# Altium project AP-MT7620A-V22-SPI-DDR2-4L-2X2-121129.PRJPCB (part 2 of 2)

## Sheet 17-GPHY1-IP1001.SchDoc
size 513 x 386 mm
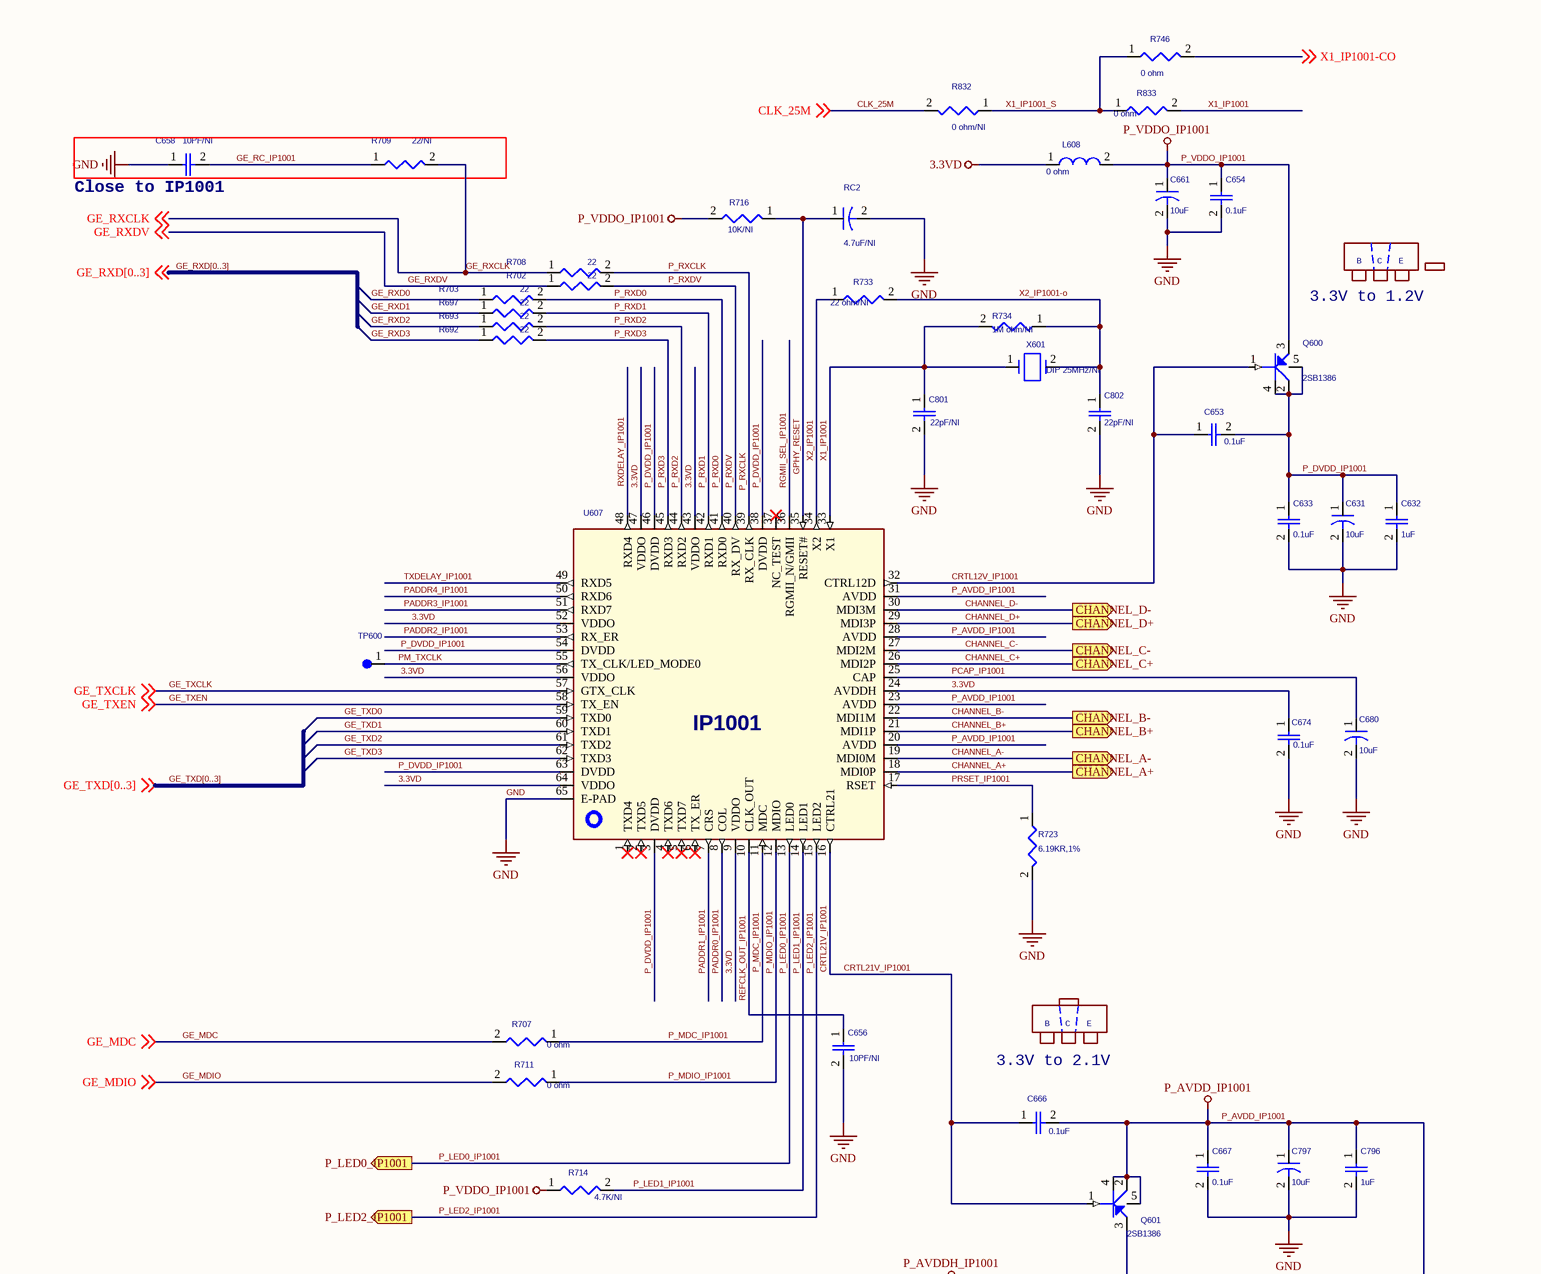
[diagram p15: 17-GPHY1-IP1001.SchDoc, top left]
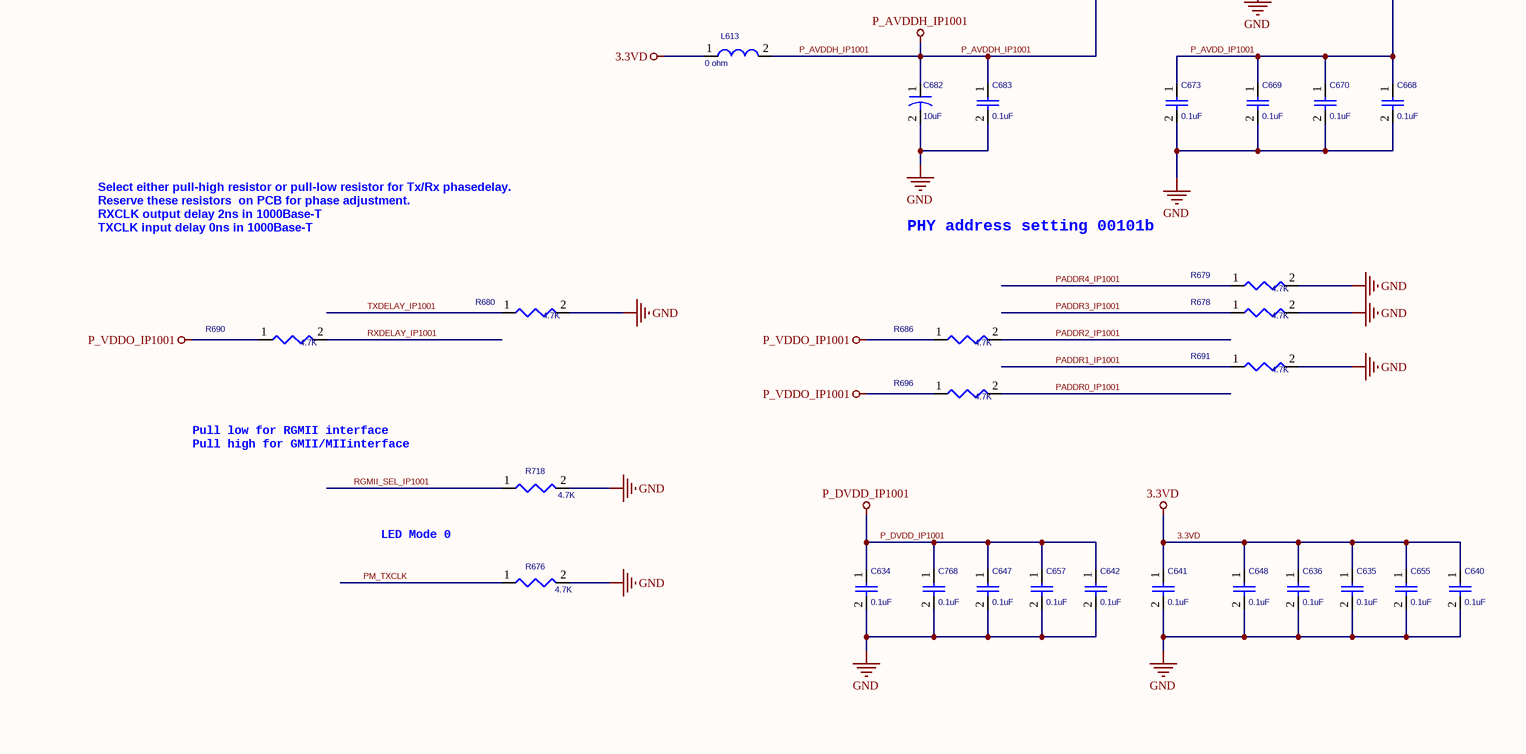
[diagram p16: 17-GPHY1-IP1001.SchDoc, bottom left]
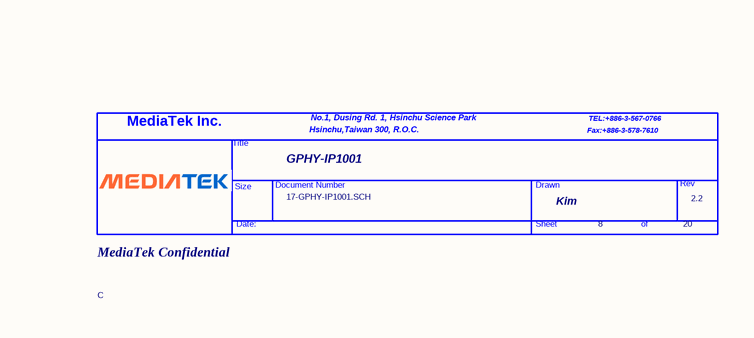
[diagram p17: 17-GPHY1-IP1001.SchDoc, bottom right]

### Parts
(Parts that share a designator on the sheet are numbered #1, #2 ... from top to bottom, then left to right.)
*#13  PIM: MediaTek Confidential  Page Count: 20  Page Number: 8  Page Size: C  Title: GPHY-IP1001  RevCode: 2.2  Doc: 17-GPHY-IP1001.SCH  Designer: Kim  (hidden comment: TitleBlock_MTK4)  (graphical)
C631  10uF  [C0805]
C632  1uF  [C0402]
C633  0.1uF  [C0402]
C634  0.1uF  [C0402]
C635  0.1uF  [C0402]
C636  0.1uF  [C0402]
C640  0.1uF  [C0402]
C641  0.1uF  [C0402]
C642  0.1uF  [C0402]
C647  0.1uF  [C0402]
C648  0.1uF  [C0402]
C653  0.1uF  [C0402]
C654  0.1uF  [C0402]
C655  0.1uF  [C0402]
C656  10PF/NI  [C0402]
C657  0.1uF  [C0402]
C658  10PF/NI  [C0402]
C661  10uF  [C0805]
C666  0.1uF  [C0402]
C667  0.1uF  [C0402]
C668  0.1uF  [C0402]
C669  0.1uF  [C0402]
C670  0.1uF  [C0402]
C673  0.1uF  [C0402]
C674  0.1uF  [C0402]
C680  10uF  [C0805]
C682  10uF  [C0805]
C683  0.1uF  [C0402]
C768  0.1uF  [C0402]
C796  1uF  [C0402]
C797  10uF  [C0805]
C801  22pF/NI  [C0402]
C802  22pF/NI  [C0402]
L608  0 ohm  [L1206]
L613  0 ohm  [L1206]
Q600  2SB1386  [SOT-89/SMD/2SB1386]
Q601  2SB1386  [SOT-89/SMD/2SB1386]
R676  4.7K  [R0402]
R678  4.7K  [R0402]
R679  4.7K  [R0402]
R680  4.7K  [R0402]
R686  4.7K  [R0402]
R690  4.7K  [R0402]
R691  4.7K  [R0402]
R692  22  [R0402]
R693  22  [R0402]
R696  4.7K  [R0402]
R697  22  [R0402]
R702  22  [R0402]
R703  22  [R0402]
R707  0 ohm  [R0402]
R708  22  [R0402]
R709  22/NI  [R0402]
R711  0 ohm  [R0402]
R714  4.7K/NI  [R0402]
R716  10K/NI  [R0402]
R718  4.7K  [R0402]
R723  6.19KR,1%  [R0402]
R733  22 ohm/NI  [R0402]
R734  1M ohm/NI  [R0402]
R746  0 ohm  [R0402]
R832  0 ohm/NI  [R0402]
R833  0 ohm  [R0402]
RC2  4.7uF/NI  [C0603]
TP600  SMD  [PAD/1P/0.5MM]  (value not drawn)
U607  IP1001  [QFN64/SMD/P0.5/IP1001]
X601  DIP 25MHz/NI  [CRYS/DIP/D5X10.6/GB2000025/eCERA]

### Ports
CHANNEL_A+ (out), CHANNEL_A- (out), CHANNEL_B+ (out), CHANNEL_B- (out), CHANNEL_C+ (out), CHANNEL_C- (out), CHANNEL_D+ (out), CHANNEL_D- (out), P_LED0_IP1001 (out), P_LED2_IP1001 (out)

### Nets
3.3VD: C635.1 C636.1 C640.1 C641.1 C648.1 C655.1 C674.1 L608.1 L613.1 U607.9(VDDO) U607.24(AVDDH) U607.43(VDDO) U607.47(VDDO) U607.52(VDDO) U607.56(VDDO) U607.64(VDDO)
GND: C631.2 C632.2 C633.2 C634.2 C635.2 C636.2 C640.2 C641.2 C642.2 C647.2 C648.2 C654.2 C655.2 C656.2 C657.2 C658.1 C661.2 C667.2 C668.2 C669.2 C670.2 C673.2 C674.2 C680.2 C682.2 C683.2 C768.2 C796.2 C797.2 C801.2 C802.2 R676.2 R678.2 R679.2 R680.2 R691.2 R718.2 R723.2 RC2.2 U607.65(E-PAD)
P_AVDD_IP1001: C666.2 C667.1 C668.1 C669.1 C670.1 C673.1 C796.1 C797.1 Q601.2(COLLECTOR) Q601.4(COLLECTOR) Q601.5(COLLECTOR) U607.20(AVDD) U607.23(AVDD) U607.28(AVDD) U607.31(AVDD)
P_AVDDH_IP1001: C682.1 C683.1 L613.2 Q601.3(EMITTER)
P_DVDD_IP1001: C631.1 C632.1 C633.1 C634.1 C642.1 C647.1 C653.2 C657.1 C768.1 Q600.2(COLLECTOR) Q600.4(COLLECTOR) Q600.5(COLLECTOR) U607.3(DVDD) U607.38(DVDD) U607.46(DVDD) U607.54(DVDD) U607.63(DVDD)
P_VDDO_IP1001: C654.1 C661.1 L608.2 Q600.3(EMITTER) R686.1 R690.1 R696.1 R714.1 R716.2
CHANNEL_A+: U607.18(MDI0P) ; port CHANNEL_A+
CHANNEL_A-: U607.19(MDI0M) ; port CHANNEL_A-
CHANNEL_B+: U607.21(MDI1P) ; port CHANNEL_B+
CHANNEL_B-: U607.22(MDI1M) ; port CHANNEL_B-
CHANNEL_C+: U607.26(MDI2P) ; port CHANNEL_C+
CHANNEL_C-: U607.27(MDI2M) ; port CHANNEL_C-
CHANNEL_D+: U607.29(MDI3P) ; port CHANNEL_D+
CHANNEL_D-: U607.30(MDI3M) ; port CHANNEL_D-
CLK_25M: R832.2 ; off-sheet CLK_25M
CRTL12V_IP1001: C653.1 Q600.1(BASE) U607.32(CTRL12D)
CRTL21V_IP1001: C666.1 Q601.1(BASE) U607.16(CTRL21)
GE_MDC: R707.2 ; off-sheet GE_MDC
GE_MDIO: R711.2 ; off-sheet GE_MDIO
GE_RC_IP1001: C658.2 R709.1
GE_RXCLK: R708.1 R709.2 ; off-sheet GE_RXCLK
GE_RXD0: R703.1
GE_RXD1: R697.1
GE_RXD2: R693.1
GE_RXD3: R692.1
GE_RXDV: R702.1 ; off-sheet GE_RXDV
GE_TXCLK: U607.57(GTX_CLK) ; off-sheet GE_TXCLK
GE_TXD0: U607.59(TXD0)
GE_TXD1: U607.60(TXD1)
GE_TXD2: U607.61(TXD2)
GE_TXD3: U607.62(TXD3)
GE_TXEN: U607.58(TX_EN) ; off-sheet GE_TXEN
GPHY_RESET: R716.1 RC2.1 U607.35(RESET#)
P_LED0_IP1001: U607.13(LED0) ; port P_LED0_IP1001
P_LED1_IP1001: R714.2 U607.14(LED1)
P_LED2_IP1001: U607.15(LED2) ; port P_LED2_IP1001
P_MDC_IP1001: R707.1 U607.11(MDC)
P_MDIO_IP1001: R711.1 U607.12(MDIO)
P_RXCLK: R708.2 U607.39(RX_CLK)
P_RXD0: R703.2 U607.41(RXD0)
P_RXD1: R697.2 U607.42(RXD1)
P_RXD2: R693.2 U607.44(RXD2)
P_RXD3: R692.2 U607.45(RXD3)
P_RXDV: R702.2 U607.40(RX_DV)
PADDR0_IP1001: R696.2 U607.8(COL)
PADDR1_IP1001: R691.1 U607.7(CRS)
PADDR2_IP1001: R686.2 U607.53(RX_ER)
PADDR3_IP1001: R678.1 U607.51(RXD7)
PADDR4_IP1001: R679.1 U607.50(RXD6)
PCAP_IP1001: C680.1 U607.25(CAP)
PM_TXCLK: R676.1 TP600.1 U607.55(TX_CLK/LED_MODE0)
PRSET_IP1001: R723.1 U607.17(RSET)
REFCLK_OUT_IP1001: C656.1 U607.10(CLK_OUT)
RGMII_SEL_IP1001: R718.1 U607.36(RGMII_N/GMII)
RXDELAY_IP1001: R690.2 U607.48(RXD4)
TXDELAY_IP1001: R680.1 U607.49(RXD5)
X1_IP1001: C801.1 R734.2 R833.2 U607.33(X1) X601.1
X1_IP1001-CO: R746.2 ; off-sheet X1_IP1001-CO
X1_IP1001_S: R746.1 R832.1 R833.1
X2_IP1001: R733.1 U607.34(X2)
X2_IP1001-o: C802.1 R733.2 R734.1 X601.2

Not connected (* = marked no-connect by the designer): U607 1(TXD4)* 2(TXD5)* 4(TXD6)* 5(TXD7)* 6(TX_ER)* 37(NC_TEST)*

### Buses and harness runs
bus GE_RXD[0..3]
bus GE_TXD[0..3]

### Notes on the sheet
- (near C658) Close to IP1001
- (near Q600) 3.3V to 1.2V
- B
- C
- E
- (near C666) 3.3V to 2.1V
- (near R680) Select either pull-high resistor or pull-low resistor for Tx/Rx phasedelay.
  Reserve these resistors  on PCB for phase adjustment.
  RXCLK output delay 2ns in 1000Base-T
  TXCLK input delay 0ns in 1000Base-T
- PHY address setting 00101b
- (near R718) Pull low for RGMII interface
  Pull high for GMII/MIIinterface
- LED Mode 0

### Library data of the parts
C631 C661 C680 C682 C797 = CAP/0805
C632-C636 C640-C642 C647 C648 C653-C657 C666-C670 C673 C674 C683 C768 C796 C801 C802 = CAP/0402_Dup2
C658 = CAP/0402_Dup1
L608 L613 = L/0805_0603
Q600 = BJT 2SB1386-PNP_2
Q601 = BJT 2SB1386-PNP_3_Dup1
R676 R678-R680 R686 R690-R693 R696 R697 R702 R703 R707-R709 R711 R714 R716 R718 R723 R733 R734 R746 R832 R833 = RES/0402_Dup2
RC2 = CAP/0603_Dup2
TP600 = TP-SMD
U607 = IP1001_0
X601 = CRYSTAL-3x9_0

## Sheet 16-MT7620A Power-F.SchDoc
size 386 x 246 mm
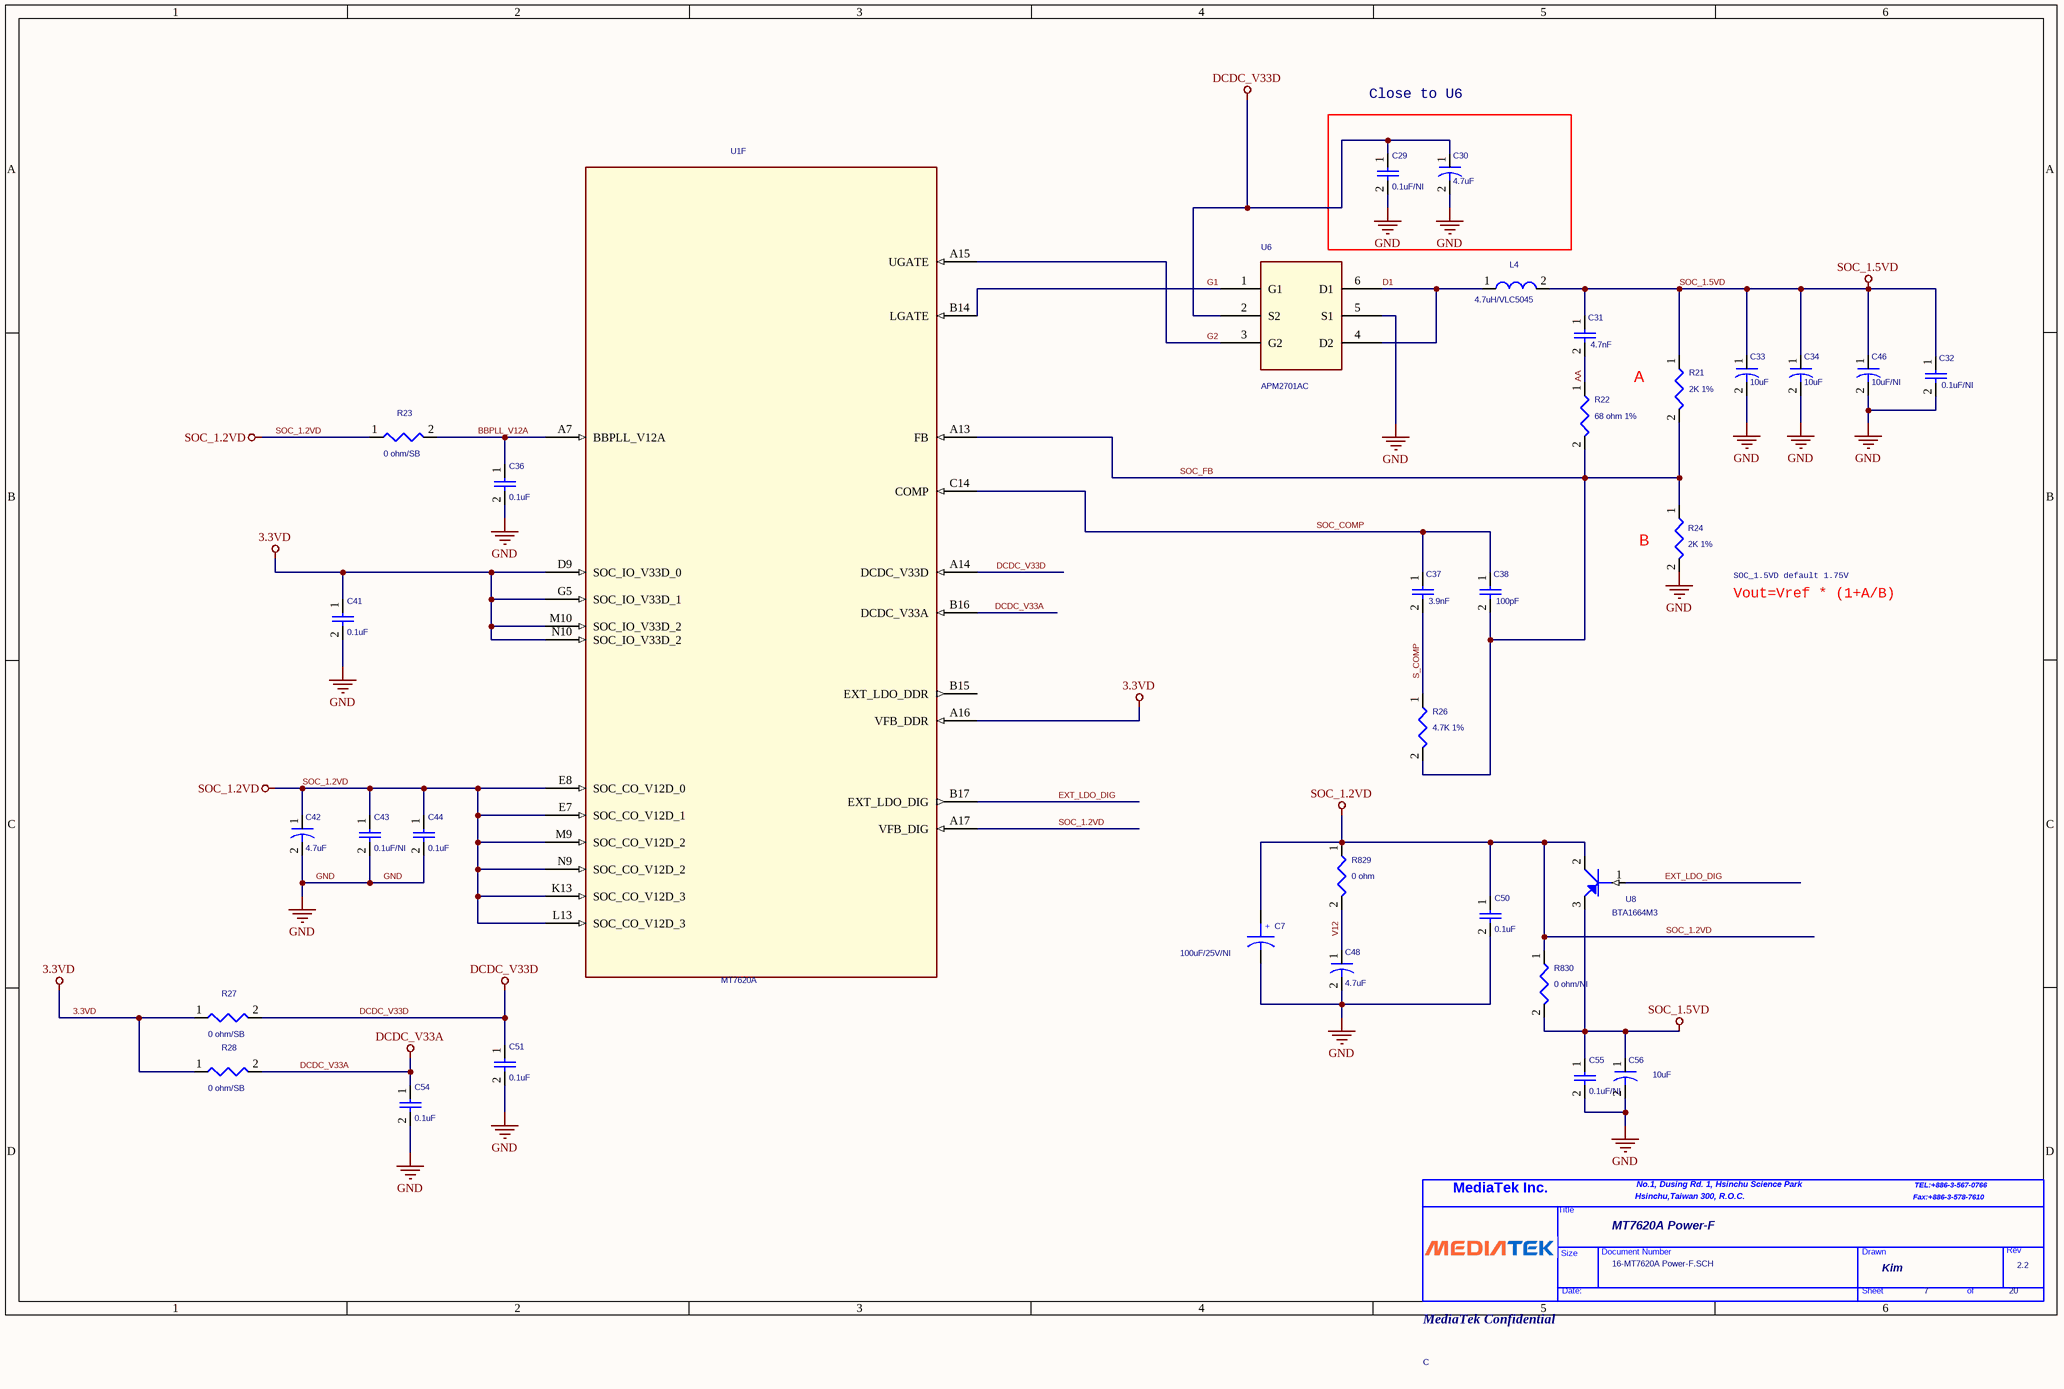
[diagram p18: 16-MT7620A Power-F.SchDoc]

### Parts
(Parts that share a designator on the sheet are numbered #1, #2 ... from top to bottom, then left to right.)
*#14  PIM: MediaTek Confidential  Page Count: 20  Page Number: 7  Page Size: C  Title: MT7620A Power-F  RevCode: 2.2  Doc: 16-MT7620A Power-F.SCH  Designer: Kim  (hidden comment: TitleBlock_MTK4)  (graphical)
C7  100uF/25V/NI  [C100UF25V/D6.3H11.5]
C29  0.1uF/NI  [C0402]
C30  4.7uF  [C0603]
C31  4.7nF  [C0402]
C32  0.1uF/NI  [C0402]
C33  10uF  [C0805]
C34  10uF  [C0805]
C36  0.1uF  [C0402]
C37  3.9nF  [C0402]
C38  100pF  [C0402]
C41  0.1uF  [C0402]
C42  4.7uF  [C0603]
C43  0.1uF/NI  [C0402]
C44  0.1uF  [C0402]
C46  10uF/NI  [C0805]
C48  4.7uF  [C0805]
C50  0.1uF  [C0402]
C51  0.1uF  [C0402]
C54  0.1uF  [C0402]
C55  0.1uF/NI  [C0402]
C56  10uF  [C0805]
L4  4.7uH/VLC5045  [L/IND/SMD/LVS5045]
R21  2K 1%  [R0402]
R22  68 ohm 1%  [R0402]
R23  0 ohm/SB  [SB/0402]
R24  2K 1%  [R0402]
R26  4.7K 1%  [R0402]
R27  0 ohm/SB  [SB/0402]
R28  0 ohm/SB  [SB/0402]
R829  0 ohm  [C0402]
R830  0 ohm/NI  [R0603]
U1  MT7620A  [MT7620AE2/TFBGA265/P0.65/B0.3/11X11]  (part F of 6)
U6  APM2701AC  [SOT-23-6/SMD/P0.95/APM2701AC]
U8  BTA1664M3  [SOT89/SMD]

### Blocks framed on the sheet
Close to U6: C29 C30

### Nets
3.3VD: C41.1 R27.1 R28.1 U1.A16(VFB_DDR) U1.D9(SOC_IO_V33D_0) U1.G5(SOC_IO_V33D_1) U1.M10(SOC_IO_V33D_2) U1.N10(SOC_IO_V33D_2)
DCDC_V33A: C54.1 R28.2 U1.B16(DCDC_V33A)
DCDC_V33D: C29.1 C30.1 C51.1 R27.2 U1.A14(DCDC_V33D) U6.2(S2)
GND: C7.2 C29.2 C30.2 C32.2 C33.2 C34.2 C36.2 C41.2 C42.2 C43.2 C44.2 C46.2 C48.2 C50.2 C51.2 C54.2 C55.2 C56.2 R24.2 U6.5(S1)
SOC_1.2VD: C7.1 C42.1 C43.1 C44.1 C50.1 R23.1 R829.1 R830.1 U1.A17(VFB_DIG) U1.E7(SOC_CO_V12D_1) U1.E8(SOC_CO_V12D_0) U1.K13(SOC_CO_V12D_3) U1.L13(SOC_CO_V12D_3) U1.M9(SOC_CO_V12D_2) U1.N9(SOC_CO_V12D_2) U8.2(COLLECTOR)
SOC_1.5VD: C31.1 C32.1 C33.1 C34.1 C46.1 C55.1 C56.1 L4.2 R21.1 R830.2 U8.3(EMITTER)
AA: C31.2 R22.1
BBPLL_V12A: C36.1 R23.2 U1.A7(BBPLL_V12A)
D1: L4.1 U6.4(D2) U6.6(D1)
EXT_LDO_DIG: U1.B17(EXT_LDO_DIG) U8.1(BASE)
G1: U1.B14(LGATE) U6.1(G1)
G2: U1.A15(UGATE) U6.3(G2)
S_COMP: C37.2 R26.1
SOC_COMP: C37.1 C38.1 U1.C14(COMP)
SOC_FB: C38.2 R21.2 R22.2 R24.1 R26.2 U1.A13(FB)
V12: C48.1 R829.2

Not connected (* = marked no-connect by the designer): U1 B15(EXT_LDO_DDR)

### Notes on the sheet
- A
- (near R24) B
- Vout=Vref * (1+A/B)
- SOC_1.5VD default 1.75V

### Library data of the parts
C7 = CAPACITOR POL
C29 C36 C41 C43 C44 C50 C51 C54 C55 = CAP/0402_0
C30 C33 C34 C46 = CAP/0603_Dup3
C31 C32 C37 C38 = CAP/0402_Dup2: 1st Part Field: 0402
C42 C48 C56 = CAP/1210_1206
L4 = L/GDR1012
R21-R24 R26-R28 R829 R830 = RES/0402_1_Dup1
U8 = BJT 2SB1386-PNP_3

## Sheet 15-MT7620A Ethernet-E.SchDoc
size 513 x 386 mm
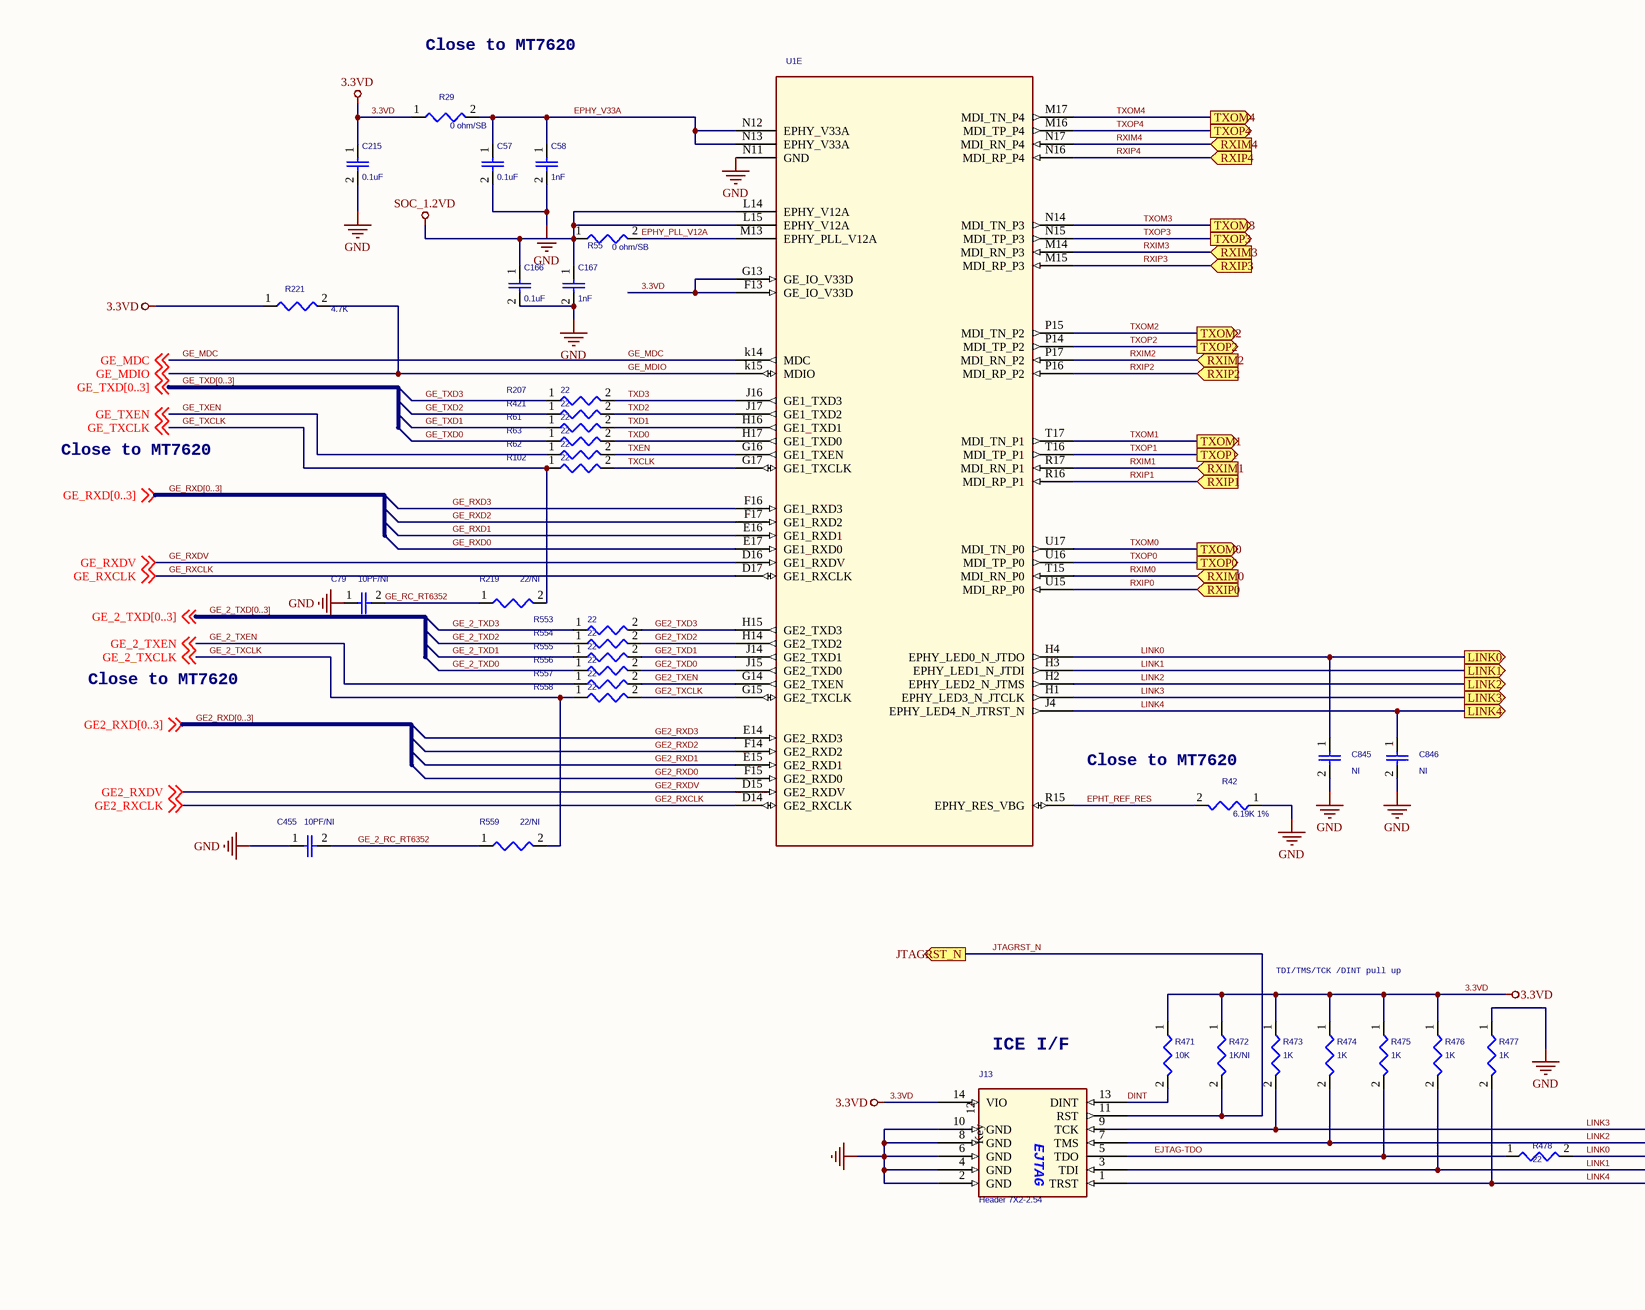
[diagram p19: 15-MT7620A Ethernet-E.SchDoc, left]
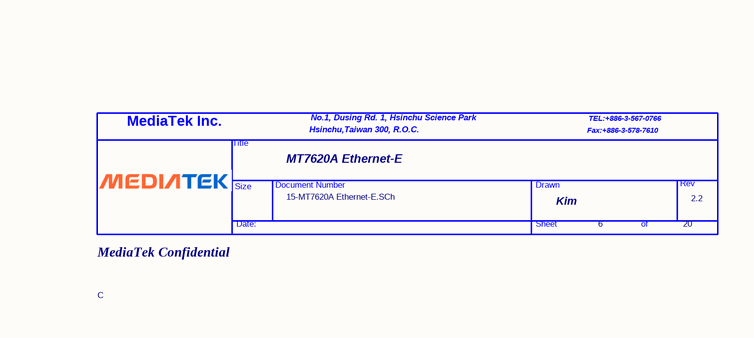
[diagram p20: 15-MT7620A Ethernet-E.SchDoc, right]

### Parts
(Parts that share a designator on the sheet are numbered #1, #2 ... from top to bottom, then left to right.)
*#15  PIM: MediaTek Confidential  Page Count: 20  Page Number: 6  Page Size: C  Title: MT7620A Ethernet-E  RevCode: 2.2  Doc: 15-MT7620A Ethernet-E.SCh  Designer: Kim  (hidden comment: TitleBlock_MTK4)  (graphical)
C57  0.1uF  [C0402]
C58  1nF  [C0402]
C79  10PF/NI  [C0402]
C166  0.1uF  [C0402]
C167  1nF  [C0402]
C215  0.1uF  [C0402]
C455  10PF/NI  [C0402]
C845  NI  [C0402]
C846  NI  [C0402]
J13  Header 7X2-2.54  [DIP7X2/P2.54]
R29  0 ohm/SB  [SB/0402]
R42  6.19K 1%  [R0402]
R55  0 ohm/SB  [SB/0402]
R61  22  [R0402]
R62  22  [R0402]
R63  22  [R0402]
R102  22  [R0402]
R207  22  [R0402]
R219  22/NI  [R0402]
R221  4.7K  [R0402]
R421  22  [R0402]
R471  10K  [R0402]
R472  1K/NI  [R0402]
R473  1K  [R0402]
R474  1K  [R0402]
R475  1K  [R0402]
R476  1K  [R0402]
R477  1K  [R0402]
R478  22  [R0402]
R553  22  [R0402]
R554  22  [R0402]
R555  22  [R0402]
R556  22  [R0402]
R557  22  [R0402]
R558  22  [R0402]
R559  22/NI  [R0402]
U1  (no value)  [MT7620AE2/TFBGA265/P0.65/B0.3/11X11]  (part E of 6)

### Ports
JTAGRST_N (out), LINK0 (out), LINK1 (out), LINK2 (out), LINK3 (out), LINK4 (out), RXIM0 (in), RXIM1 (in), RXIM2 (in), RXIM3 (in), RXIM4 (in), RXIP0 (in), RXIP1 (in), RXIP2 (in), RXIP3 (in), RXIP4 (in), TXOM0 (out), TXOM1 (out), TXOM2 (out), TXOM3 (out), TXOM4 (out), TXOP0 (out), TXOP1 (out), TXOP2 (out), TXOP3 (out), TXOP4 (out)

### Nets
3.3VD: C215.1 J13.14(VIO) R29.1 R221.1 R471.1 R472.1 R473.1 R474.1 R475.1 R476.1 U1.F13(GE_IO_V33D) U1.G13(GE_IO_V33D)
GND: C57.2 C58.2 C79.1 C166.2 C167.2 C215.2 C455.1 C845.2 C846.2 J13.2(GND) J13.4(GND) J13.6(GND) J13.8(GND) J13.10(GND) R42.1 R477.1 U1.N11(GND)
SOC_1.2VD: C166.1 C167.1 R55.1 U1.L14(EPHY_V12A) U1.L15(EPHY_V12A)
DINT: J13.13(DINT) R471.2
EJTAG-TDO: J13.5(TDO) R475.2 R478.1
EPHT_REF_RES: R42.2 U1.R15(EPHY_RES_VBG)
EPHY_PLL_V12A: R55.2 U1.M13(EPHY_PLL_V12A)
EPHY_V33A: C57.1 C58.1 R29.2 U1.N12(EPHY_V33A) U1.N13(EPHY_V33A)
GE2_RXCLK: U1.D14(GE2_RXCLK) ; off-sheet GE2_RXCLK
GE2_RXD0: U1.F15(GE2_RXD0)
GE2_RXD1: U1.E15(GE2_RXD1)
GE2_RXD2: U1.F14(GE2_RXD2)
GE2_RXD3: U1.E14(GE2_RXD3)
GE2_RXDV: U1.D15(GE2_RXDV) ; off-sheet GE2_RXDV
GE2_TXCLK: R558.2 U1.G15(GE2_TXCLK)
GE2_TXD0: R556.2 U1.J15(GE2_TXD0)
GE2_TXD1: R555.2 U1.J14(GE2_TXD1)
GE2_TXD2: R554.2 U1.H14(GE2_TXD2)
GE2_TXD3: R553.2 U1.H15(GE2_TXD3)
GE2_TXEN: R557.2 U1.G14(GE2_TXEN)
GE_2_RC_RT6352: C455.2 R559.1
GE_2_TXCLK: R558.1 R559.2 ; off-sheet GE_2_TXCLK
GE_2_TXD0: R556.1
GE_2_TXD1: R555.1
GE_2_TXD2: R554.1
GE_2_TXD3: R553.1
GE_2_TXEN: R557.1 ; off-sheet GE_2_TXEN
GE_MDC: U1.k14(MDC) ; off-sheet GE_MDC
GE_MDIO: R221.2 U1.k15(MDIO) ; off-sheet GE_MDIO
GE_RC_RT6352: C79.2 R219.1
GE_RXCLK: U1.D17(GE1_RXCLK) ; off-sheet GE_RXCLK
GE_RXD0: U1.E17(GE1_RXD0)
GE_RXD1: U1.E16(GE1_RXD1)
GE_RXD2: U1.F17(GE1_RXD2)
GE_RXD3: U1.F16(GE1_RXD3)
GE_RXDV: U1.D16(GE1_RXDV) ; off-sheet GE_RXDV
GE_TXCLK: R102.1 R219.2 ; off-sheet GE_TXCLK
GE_TXD0: R63.1
GE_TXD1: R61.1
GE_TXD2: R421.1
GE_TXD3: R207.1
GE_TXEN: R62.1 ; off-sheet GE_TXEN
JTAGRST_N: J13.11(RST) R472.2 ; port JTAGRST_N
LINK0: C845.1 R478.2 U1.H4(EPHY_LED0_N_JTDO) ; port LINK0
LINK1: J13.3(TDI) R476.2 U1.H3(EPHY_LED1_N_JTDI) ; port LINK1
LINK2: J13.7(TMS) R474.2 U1.H2(EPHY_LED2_N_JTMS) ; port LINK2
LINK3: J13.9(TCK) R473.2 U1.H1(EPHY_LED3_N_JTCLK) ; port LINK3
LINK4: C846.1 J13.1(TRST) R477.2 U1.J4(EPHY_LED4_N_JTRST_N) ; port LINK4
RXIM0: U1.T15(MDI_RN_P0) ; port RXIM0
RXIM1: U1.R17(MDI_RN_P1) ; port RXIM1
RXIM2: U1.P17(MDI_RN_P2) ; port RXIM2
RXIM3: U1.M14(MDI_RN_P3) ; port RXIM3
RXIM4: U1.N17(MDI_RN_P4) ; port RXIM4
RXIP0: U1.U15(MDI_RP_P0) ; port RXIP0
RXIP1: U1.R16(MDI_RP_P1) ; port RXIP1
RXIP2: U1.P16(MDI_RP_P2) ; port RXIP2
RXIP3: U1.M15(MDI_RP_P3) ; port RXIP3
RXIP4: U1.N16(MDI_RP_P4) ; port RXIP4
TXCLK: R102.2 U1.G17(GE1_TXCLK)
TXD0: R63.2 U1.H17(GE1_TXD0)
TXD1: R61.2 U1.H16(GE1_TXD1)
TXD2: R421.2 U1.J17(GE1_TXD2)
TXD3: R207.2 U1.J16(GE1_TXD3)
TXEN: R62.2 U1.G16(GE1_TXEN)
TXOM0: U1.U17(MDI_TN_P0) ; port TXOM0
TXOM1: U1.T17(MDI_TN_P1) ; port TXOM1
TXOM2: U1.P15(MDI_TN_P2) ; port TXOM2
TXOM3: U1.N14(MDI_TN_P3) ; port TXOM3
TXOM4: U1.M17(MDI_TN_P4) ; port TXOM4
TXOP0: U1.U16(MDI_TP_P0) ; port TXOP0
TXOP1: U1.T16(MDI_TP_P1) ; port TXOP1
TXOP2: U1.P14(MDI_TP_P2) ; port TXOP2
TXOP3: U1.N15(MDI_TP_P3) ; port TXOP3
TXOP4: U1.M16(MDI_TP_P4) ; port TXOP4

Not connected (* = marked no-connect by the designer): J13 12(Key)

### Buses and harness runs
bus GE2_RXD[0..3]
bus GE_2_TXD[0..3]
bus GE_RXD[0..3]
bus GE_TXD[0..3]

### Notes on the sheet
- Close to MT7620
- TDI/TMS/TCK /DINT pull up
- (near J13) ICE I/F

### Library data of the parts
C57 C58 C166 C167 C215 = CAP/0402_1
C79 C455 = CAP/0402_Dup1
C845 C846 = CAP/0402
J13 = HEADER 7x2-male
R29 R55 = RES/0402_5
R42 = RES/0402_3
R61-R63 R102 R207 R219 R221 R421 R553-R559 = RES/0402_Dup2
R471-R478 = RES/0402_Dup1
U1 = MT7620A

## Sheet 14-MT7620A USB and PCIE.SchDoc
size 386 x 246 mm
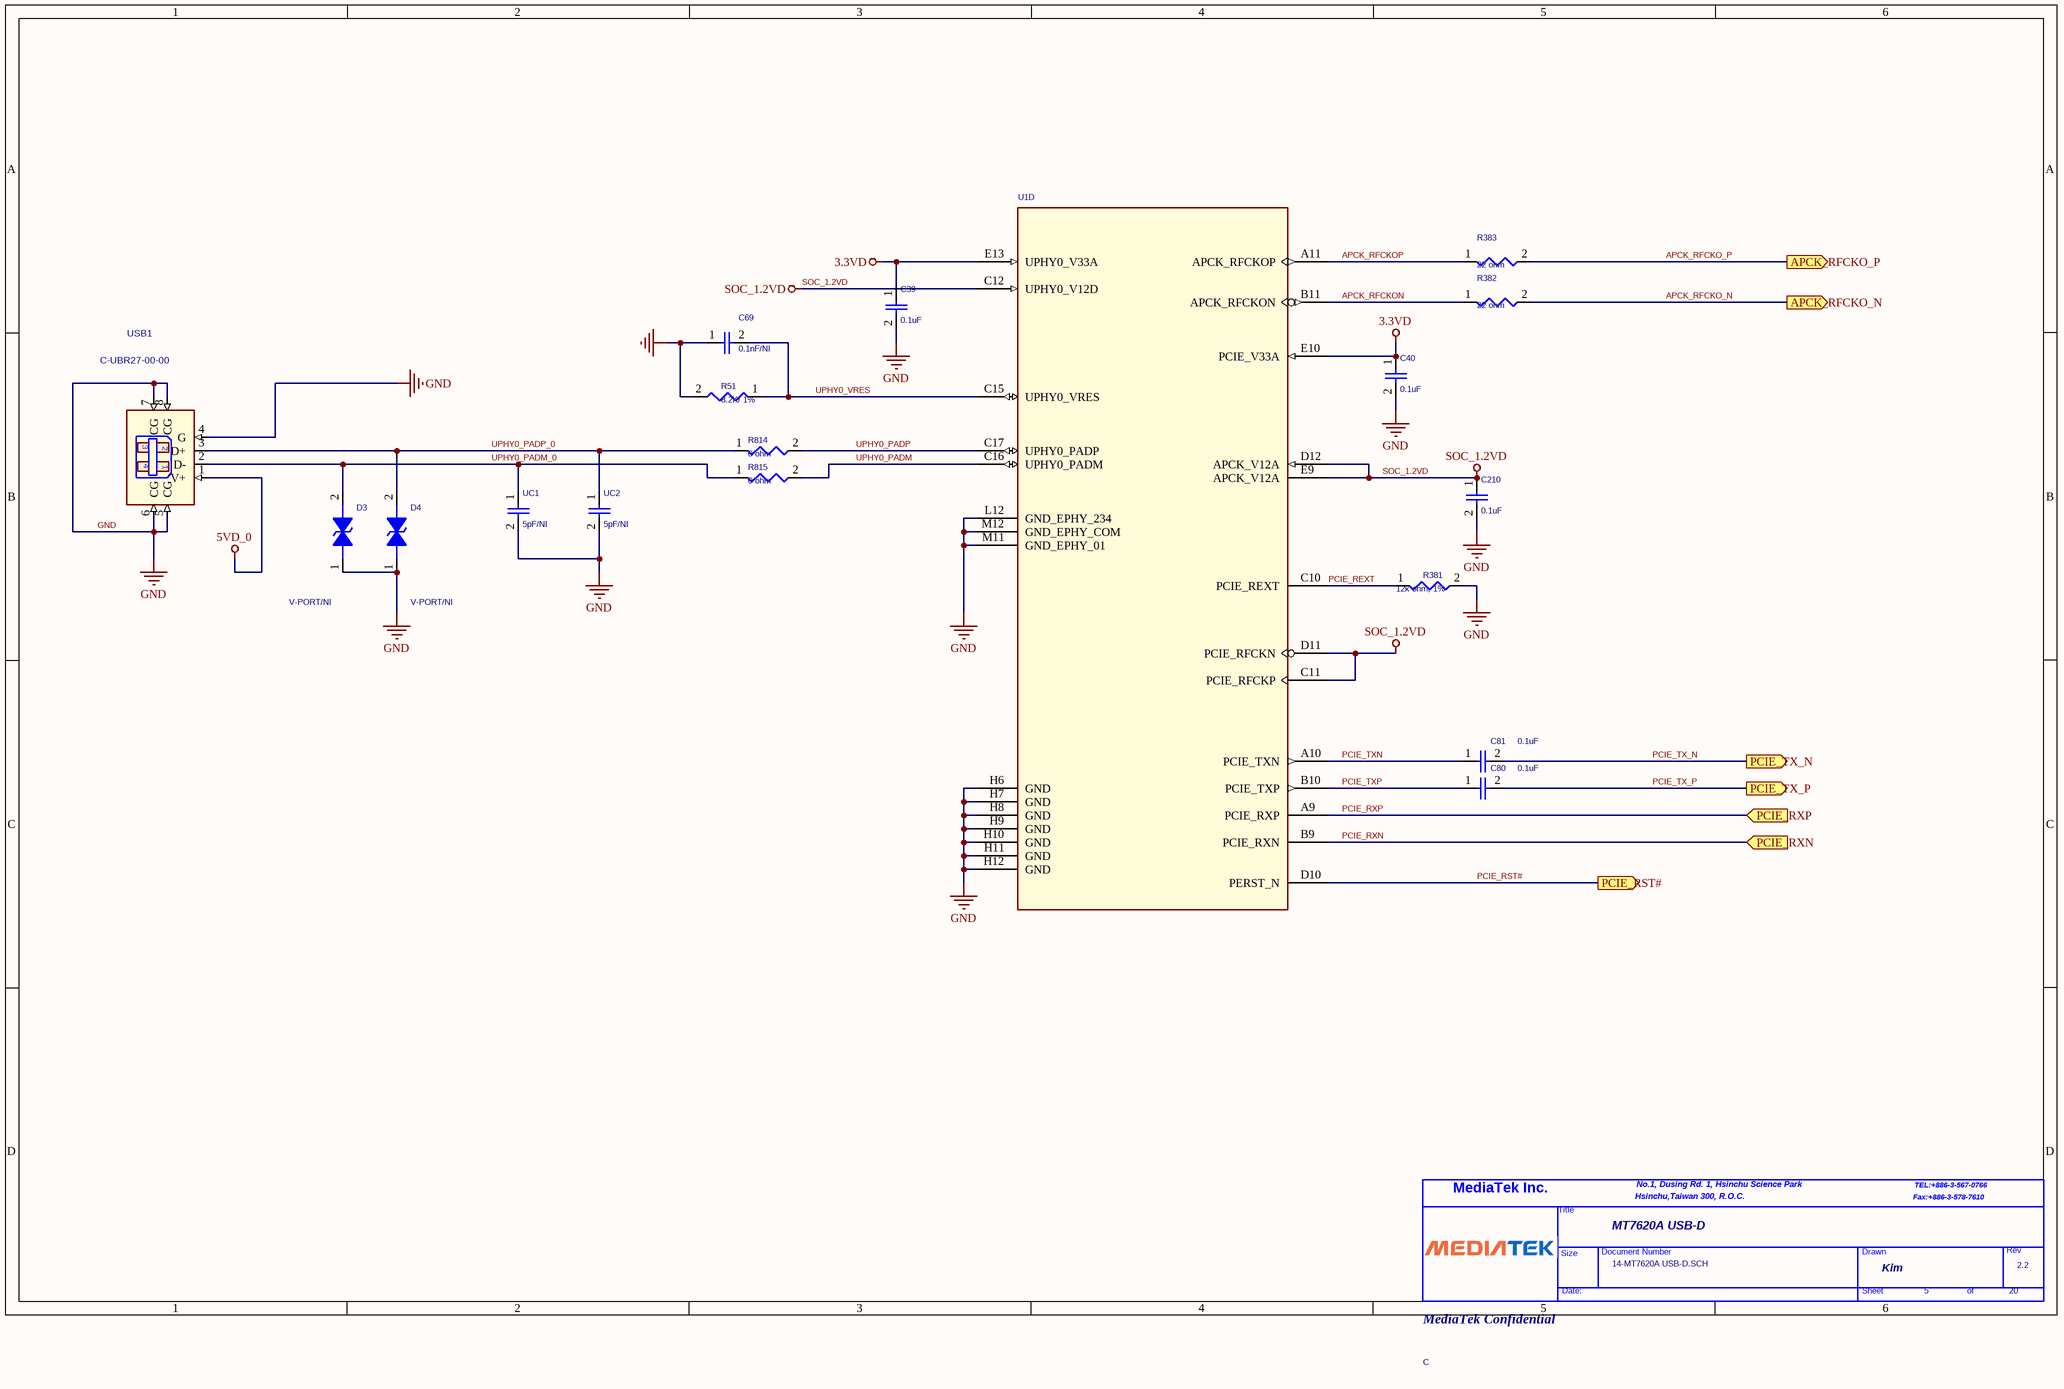
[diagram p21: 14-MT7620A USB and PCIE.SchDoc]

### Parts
(Parts that share a designator on the sheet are numbered #1, #2 ... from top to bottom, then left to right.)
*#16  PIM: MediaTek Confidential  Page Count: 20  Page Number: 5  Page Size: C  Title: MT7620A USB-D  RevCode: 2.2  Doc: 14-MT7620A USB-D.SCH  Designer: Kim  (hidden comment: TitleBlock_MTK4)  (graphical)
C39  0.1uF  [C0402]
C40  0.1uF  [C0402]
C69  0.1nF/NI  [C0402]
C80  0.1uF  [C0402]
C81  0.1uF  [C0402]
C210  0.1uF  [C0402]
D3  V-PORT/NI  [C0603]
D4  V-PORT/NI  [C0603]
R51  8.2K/ 1%  [R0402]
R381  12k ohm, 1%  [R0402]
R382  22 ohm  [R0402]
R383  22 ohm  [R0402]
R814  0 ohm  [R0402]
R815  0 ohm  [R0402]
U1  (no value)  [MT7620AE2/TFBGA265/P0.65/B0.3/11X11]  (part D of 6)
UC1  5pF/NI  [C0402]
UC2  5pF/NI  [C0402]
USB1  C-UBR27-00-00  [USB/4P/P2.0/DIP/R/F/SUA-110VB-B2N]

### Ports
APCK_RFCKO_N (out), APCK_RFCKO_P (out), PCIE_RST# (out), PCIE_RXN (in), PCIE_RXP (in), PCIE_TX_N (out), PCIE_TX_P (out)

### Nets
3.3VD: C39.1 C40.1 U1.E10(PCIE_V33A) U1.E13(UPHY0_V33A)
5VD_0: USB1.1(V+)
GND: C39.2 C40.2 C69.1 C210.2 D3.1 D4.1 R51.2 R381.2 U1.H6(GND) U1.H7(GND) U1.H8(GND) U1.H9(GND) U1.H10(GND) U1.H11(GND) U1.H12(GND) U1.L12(GND_EPHY_234) U1.M11(GND_EPHY_01) U1.M12(GND_EPHY_COM) UC1.2 UC2.2 USB1.4(G) USB1.5(CG) USB1.6(CG) USB1.7(CG) USB1.8(CG)
SOC_1.2VD: C210.1 U1.C11(PCIE_RFCKP) U1.C12(UPHY0_V12D) U1.D11(PCIE_RFCKN) U1.D12(APCK_V12A) U1.E9(APCK_V12A)
APCK_RFCKO_N: R382.2 ; port APCK_RFCKO_N
APCK_RFCKO_P: R383.2 ; port APCK_RFCKO_P
APCK_RFCKON: R382.1 U1.B11(APCK_RFCKON)
APCK_RFCKOP: R383.1 U1.A11(APCK_RFCKOP)
PCIE_REXT: R381.1 U1.C10(PCIE_REXT)
PCIE_RST#: U1.D10(PERST_N) ; port PCIE_RST#
PCIE_RXN: U1.B9(PCIE_RXN) ; port PCIE_RXN
PCIE_RXP: U1.A9(PCIE_RXP) ; port PCIE_RXP
PCIE_TX_N: C81.2 ; port PCIE_TX_N
PCIE_TX_P: C80.2 ; port PCIE_TX_P
PCIE_TXN: C81.1 U1.A10(PCIE_TXN)
PCIE_TXP: C80.1 U1.B10(PCIE_TXP)
UPHY0_PADM: R815.2 U1.C16(UPHY0_PADM)
UPHY0_PADM_0: D3.2 R815.1 UC1.1 USB1.2(D-)
UPHY0_PADP: R814.2 U1.C17(UPHY0_PADP)
UPHY0_PADP_0: D4.2 R814.1 UC2.1 USB1.3(D+)
UPHY0_VRES: C69.2 R51.1 U1.C15(UPHY0_VRES)

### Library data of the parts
C39 C40 C210 = CAP/0402_0
C69 C80 C81 UC1 UC2 = CAP/0402_1
D3 D4 = DIODE DIAC: PartNo: 3500-00000530
R51 R381-R383 R814 R815 = RES/0402_3
U1 = MT7620A
USB1 = USB_A-RECEPT-DIP: Schematics' Source Library: C:\MSim_8\UserLib\vnet2.slb

## Sheet 13-MT7620A Peripheral-C.SchDoc
size 386 x 246 mm
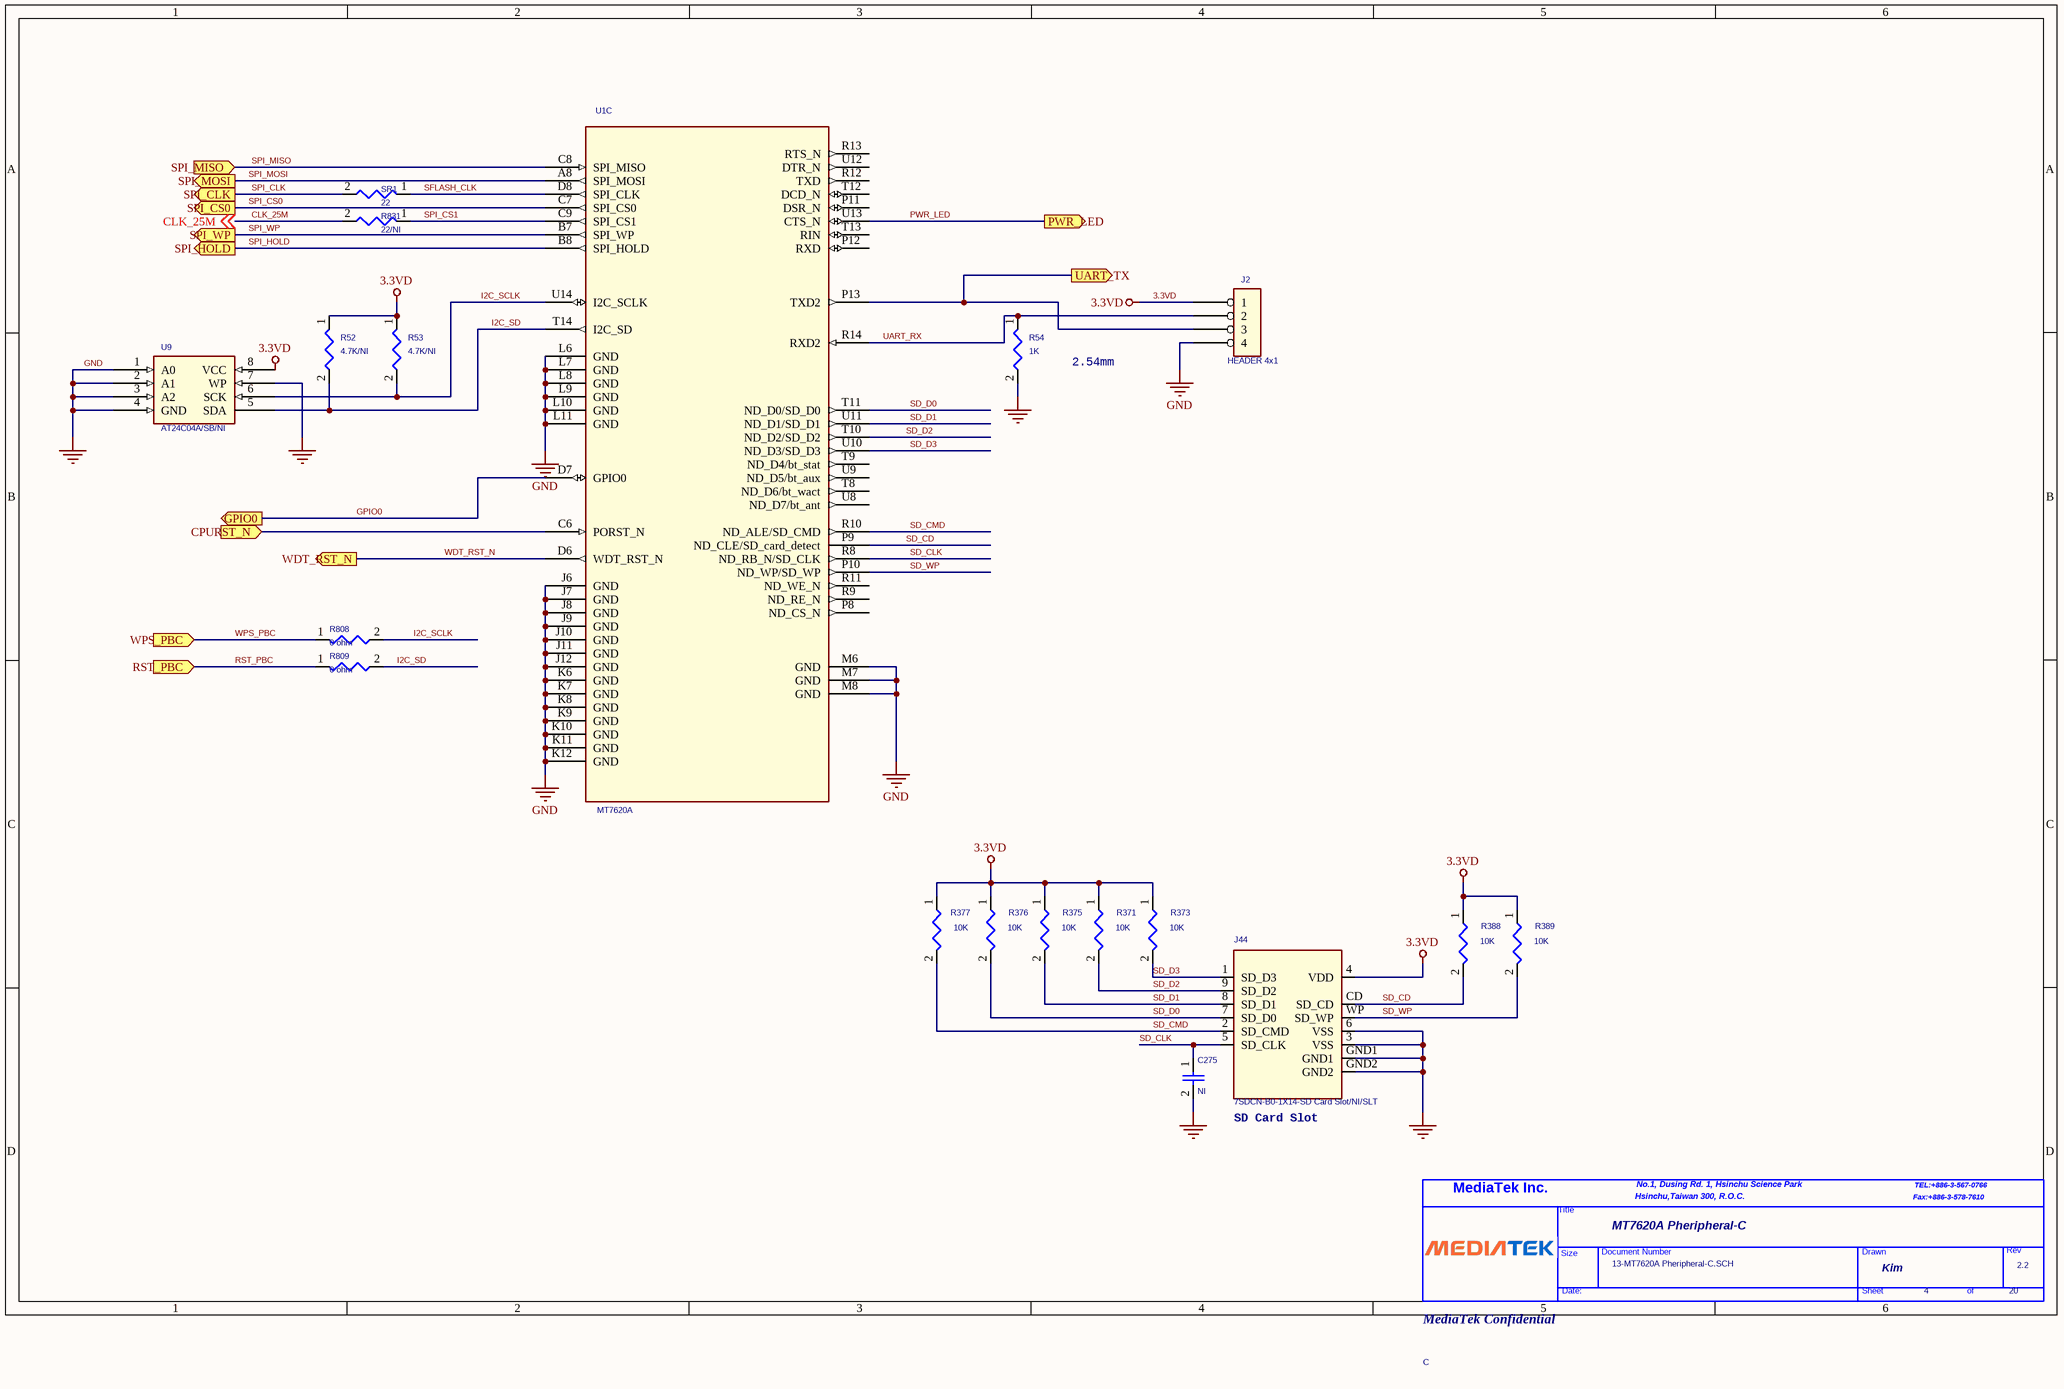
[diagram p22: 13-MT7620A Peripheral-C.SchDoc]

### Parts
(Parts that share a designator on the sheet are numbered #1, #2 ... from top to bottom, then left to right.)
*#17  PIM: MediaTek Confidential  Page Count: 20  Page Number: 4  Page Size: C  Title: MT7620A Pheripheral-C  RevCode: 2.2  Doc: 13-MT7620A Pheripheral-C.SCH  Designer: Kim  (hidden comment: TitleBlock_MTK4)  (graphical)
C275  NI  [C0402]
J2  HEADER 4x1  [DIP4/P2.54]
J44  7SDCN-B0-1X14-SD Card Slot/NI/SLT  [CON10P/SMD/R/F/7SDCN-B0-1X14]
R52  4.7K/NI  [R0402]
R53  4.7K/NI  [R0402]
R54  1K  [R0402]
R371  10K  [R0402]
R373  10K  [R0402]
R375  10K  [R0402]
R376  10K  [R0402]
R377  10K  [R0402]
R388  10K  [R0402]
R389  10K  [R0402]
R808  0 ohm  [R0402]
R809  0 ohm  [R0402]
R831  22/NI  [R0402]
SR1  22  [R0402]
U1  MT7620A  [MT7620AE2/TFBGA265/P0.65/B0.3/11X11]  (part C of 6)
U9  AT24C04A/SB/NI  [SOIC8/SMD/P1.27/AT24C04B-08B]

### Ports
CPURST_N (in), GPIO0 (out), PWR_LED (out), RST_PBC (in), SPI_CLK (out), SPI_CS0 (out), SPI_HOLD (out), SPI_MISO (in), SPI_MOSI (out), SPI_WP (out), UART_TX (out), WDT_RST_N (out), WPS_PBC (in)

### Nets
3.3VD: J2.1 J44.4(VDD) R52.1 R53.1 R371.1 R373.1 R375.1 R376.1 R377.1 R388.1 R389.1 U9.8(VCC)
GND: C275.2 J2.4 J44.3(VSS) J44.6(VSS) J44.GND1 J44.GND2 R54.2 U1.J6(GND) U1.J7(GND) U1.J8(GND) U1.J9(GND) U1.J10(GND) U1.J11(GND) U1.J12(GND) U1.K6(GND) U1.K7(GND) U1.K8(GND) U1.K9(GND) U1.K10(GND) U1.K11(GND) U1.K12(GND) U1.L6(GND) U1.L7(GND) U1.L8(GND) U1.L9(GND) U1.L10(GND) U1.L11(GND) U1.M6(GND) U1.M7(GND) U1.M8(GND) U9.1(A0) U9.2(A1) U9.3(A2) U9.4(GND) U9.7(WP)
CLK_25M: R831.2 ; off-sheet CLK_25M
CPURST_N: U1.C6(PORST_N) ; port CPURST_N
GPIO0: U1.D7(GPIO0) ; port GPIO0
I2C_SCLK: R53.2 R808.2 U1.U14(I2C_SCLK) U9.6(SCK)
I2C_SD: R52.2 R809.2 U1.T14(I2C_SD) U9.5(SDA)
PWR_LED: U1.U13(CTS_N) ; port PWR_LED
RST_PBC: R809.1 ; port RST_PBC
SD_CD: J44.CD(SD_CD) R388.2 U1.P9(ND_CLE/SD_card_detect)
SD_CLK: C275.1 J44.5(SD_CLK) U1.R8(ND_RB_N/SD_CLK)
SD_CMD: J44.2(SD_CMD) R377.2 U1.R10(ND_ALE/SD_CMD)
SD_D0: J44.7(SD_D0) R376.2 U1.T11(ND_D0/SD_D0)
SD_D1: J44.8(SD_D1) R375.2 U1.U11(ND_D1/SD_D1)
SD_D2: J44.9(SD_D2) R371.2 U1.T10(ND_D2/SD_D2)
SD_D3: J44.1(SD_D3) R373.2 U1.U10(ND_D3/SD_D3)
SD_WP: J44.WP(SD_WP) R389.2 U1.P10(ND_WP/SD_WP)
SFLASH_CLK: SR1.1 U1.D8(SPI_CLK)
SPI_CLK: SR1.2 ; port SPI_CLK
SPI_CS0: U1.C7(SPI_CS0) ; port SPI_CS0
SPI_CS1: R831.1 U1.C9(SPI_CS1)
SPI_HOLD: U1.B8(SPI_HOLD) ; port SPI_HOLD
SPI_MISO: U1.C8(SPI_MISO) ; port SPI_MISO
SPI_MOSI: U1.A8(SPI_MOSI) ; port SPI_MOSI
SPI_WP: U1.B7(SPI_WP) ; port SPI_WP
UART_RX: J2.2 R54.1 U1.R14(RXD2)
UART_TX: J2.3 U1.P13(TXD2) ; port UART_TX
WDT_RST_N: U1.D6(WDT_RST_N) ; port WDT_RST_N
WPS_PBC: R808.1 ; port WPS_PBC

Not connected (* = marked no-connect by the designer): U1 P8(ND_CS_N) P11(DSR_N) P12(RXD) R9(ND_RE_N) R11(ND_WE_N) R12(TXD) R13(RTS_N) T8(ND_D6/bt_wact) T9(ND_D4/bt_stat) T12(DCD_N) T13(RIN) U8(ND_D7/bt_ant) U9(ND_D5/bt_aux) U12(DTR_N)

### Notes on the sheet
- 2.54mm
- SD Card Slot

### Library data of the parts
C275 = C0402
J2 = HEADER 4x1_0
J44 = 7SDCN-B0-1X14-SD Card Slot
R52-R54 R831 SR1 = RES/0402_3
R371 R373 R375-R377 R388 R389 = R0402
R808 R809 = RES/0402
U9 = Mem AT24C02_0

## Sheet 12-MT7620A DDR I_F-B.SchDoc
size 386 x 246 mm
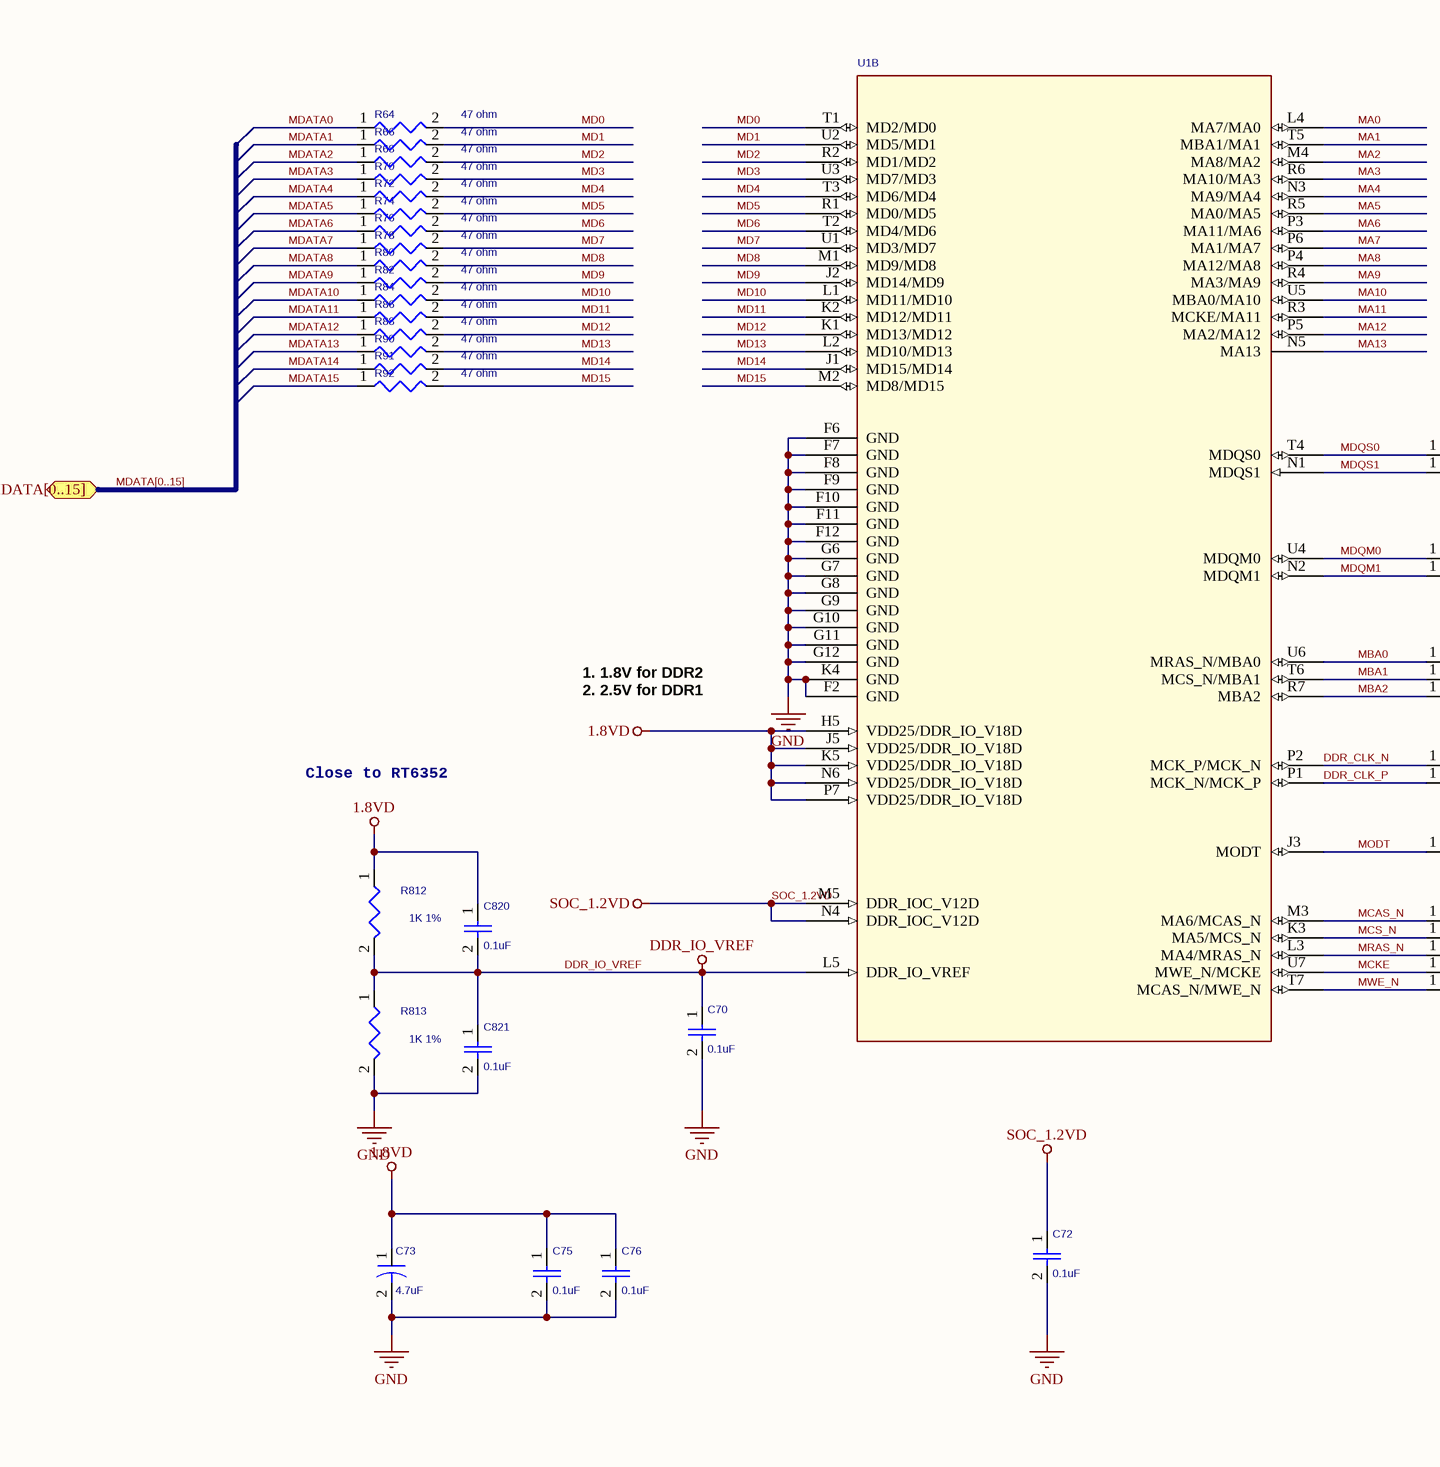
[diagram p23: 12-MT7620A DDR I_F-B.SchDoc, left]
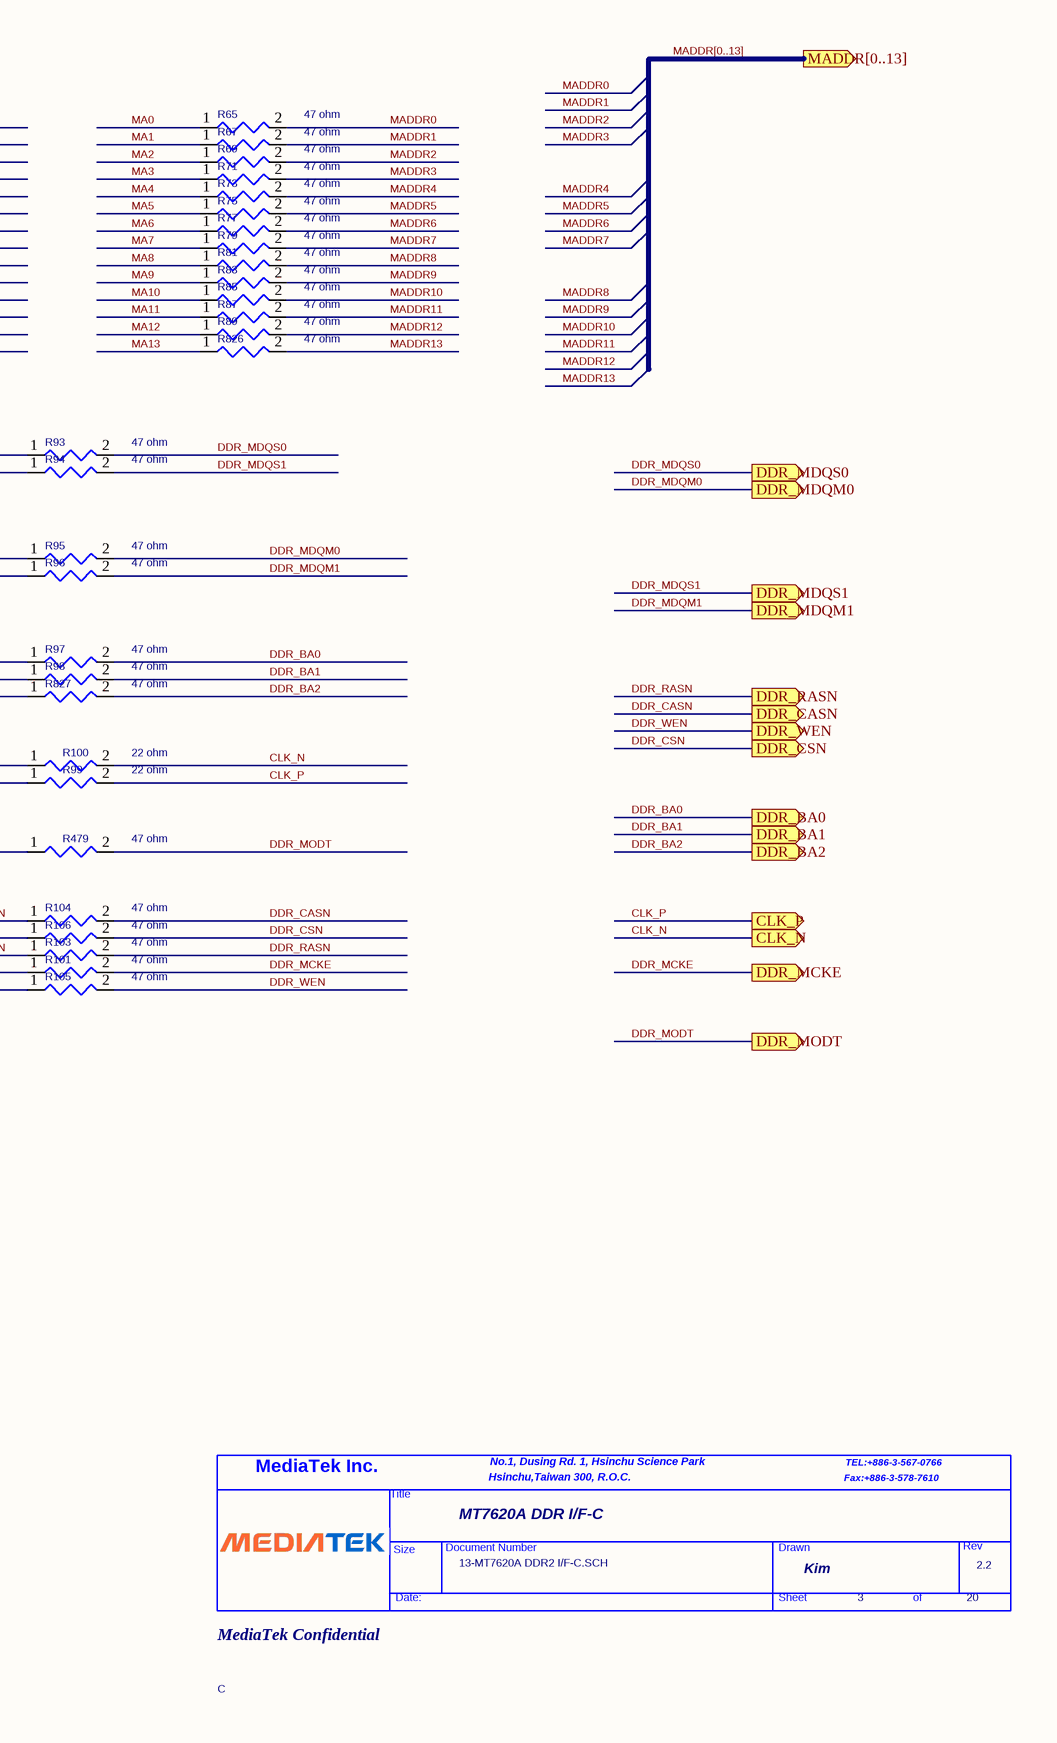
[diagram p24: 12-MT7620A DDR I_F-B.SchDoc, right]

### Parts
(Parts that share a designator on the sheet are numbered #1, #2 ... from top to bottom, then left to right.)
*#18  PIM: MediaTek Confidential  Page Count: 20  Page Number: 3  Page Size: C  Title: MT7620A DDR I/F-C  RevCode: 2.2  Doc: 13-MT7620A DDR2 I/F-C.SCH  Designer: Kim  (hidden comment: TitleBlock_MTK4)  (graphical)
C70  0.1uF  [C0402]
C72  0.1uF  [C0402]
C73  4.7uF  [C0805]
C75  0.1uF  [C0402]
C76  0.1uF  [C0402]
C820  0.1uF  [C0402]
C821  0.1uF  [C0402]
R64  47 ohm  [R0402]
R65  47 ohm  [R0402]
R66  47 ohm  [R0402]
R67  47 ohm  [R0402]
R68  47 ohm  [R0402]
R69  47 ohm  [R0402]
R70  47 ohm  [R0402]
R71  47 ohm  [R0402]
R72  47 ohm  [R0402]
R73  47 ohm  [R0402]
R74  47 ohm  [R0402]
R75  47 ohm  [R0402]
R76  47 ohm  [R0402]
R77  47 ohm  [R0402]
R78  47 ohm  [R0402]
R79  47 ohm  [R0402]
R80  47 ohm  [R0402]
R81  47 ohm  [R0402]
R82  47 ohm  [R0402]
R83  47 ohm  [R0402]
R84  47 ohm  [R0402]
R85  47 ohm  [R0402]
R86  47 ohm  [R0402]
R87  47 ohm  [R0402]
R88  47 ohm  [R0402]
R89  47 ohm  [R0402]
R90  47 ohm  [R0402]
R91  47 ohm  [R0402]
R92  47 ohm  [R0402]
R93  47 ohm  [R0402]
R94  47 ohm  [R0402]
R95  47 ohm  [R0402]
R96  47 ohm  [R0402]
R97  47 ohm  [R0402]
R98  47 ohm  [R0402]
R99  22 ohm  [R0402]
R100  22 ohm  [R0402]
R101  47 ohm  [R0402]
R103  47 ohm  [R0402]
R104  47 ohm  [R0402]
R105  47 ohm  [R0402]
R106  47 ohm  [R0402]
R479  47 ohm  [R0402]
R812  1K 1%  [R0402]
R813  1K 1%  [R0402]
R826  47 ohm  [R0402]
R827  47 ohm  [R0402]
U1  (no value)  [MT7620AE2/TFBGA265/P0.65/B0.3/11X11]  (part B of 6)

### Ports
CLK_N (out), CLK_P (out), DDR_BA0 (out), DDR_BA1 (out), DDR_BA2 (out), DDR_CASN (out), DDR_CSN (out), DDR_MCKE (out), DDR_MDQM0 (out), DDR_MDQM1 (out), DDR_MDQS0 (out), DDR_MDQS1 (out), DDR_MODT (out), DDR_RASN (out), DDR_WEN (out), MADDR[0..13] (out), MDATA[0..15] (bidir)

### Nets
1.8VD: C73.1 C75.1 C76.1 C820.1 R812.1 U1.H5(VDD25/DDR_IO_V18D) U1.J5(VDD25/DDR_IO_V18D) U1.K5(VDD25/DDR_IO_V18D) U1.N6(VDD25/DDR_IO_V18D) U1.P7(VDD25/DDR_IO_V18D)
DDR_IO_VREF: C70.1 C820.2 C821.1 R812.2 R813.1 U1.L5(DDR_IO_VREF)
GND: C70.2 C72.2 C73.2 C75.2 C76.2 C821.2 R813.2 U1.F2(GND) U1.F6(GND) U1.F7(GND) U1.F8(GND) U1.F9(GND) U1.F10(GND) U1.F11(GND) U1.F12(GND) U1.G6(GND) U1.G7(GND) U1.G8(GND) U1.G9(GND) U1.G10(GND) U1.G11(GND) U1.G12(GND) U1.K4(GND)
SOC_1.2VD: C72.1 U1.M5(DDR_IOC_V12D) U1.N4(DDR_IOC_V12D)
CLK_N: R100.2 ; port CLK_N
CLK_P: R99.2 ; port CLK_P
DDR_BA0: R97.2 ; port DDR_BA0
DDR_BA1: R98.2 ; port DDR_BA1
DDR_BA2: R827.2 ; port DDR_BA2
DDR_CASN: R104.2 ; port DDR_CASN
DDR_CLK_N: R100.1 U1.P2(MCK_P/MCK_N)
DDR_CLK_P: R99.1 U1.P1(MCK_N/MCK_P)
DDR_CSN: R106.2 ; port DDR_CSN
DDR_MCKE: R101.2 ; port DDR_MCKE
DDR_MDQM0: R95.2 ; port DDR_MDQM0
DDR_MDQM1: R96.2 ; port DDR_MDQM1
DDR_MDQS0: R93.2 ; port DDR_MDQS0
DDR_MDQS1: R94.2 ; port DDR_MDQS1
DDR_MODT: R479.2 ; port DDR_MODT
DDR_RASN: R103.2 ; port DDR_RASN
DDR_WEN: R105.2 ; port DDR_WEN
MA0: R65.1 U1.L4(MA7/MA0)
MA1: R67.1 U1.T5(MBA1/MA1)
MA2: R69.1 U1.M4(MA8/MA2)
MA3: R71.1 U1.R6(MA10/MA3)
MA4: R73.1 U1.N3(MA9/MA4)
MA5: R75.1 U1.R5(MA0/MA5)
MA6: R77.1 U1.P3(MA11/MA6)
MA7: R79.1 U1.P6(MA1/MA7)
MA8: R81.1 U1.P4(MA12/MA8)
MA9: R83.1 U1.R4(MA3/MA9)
MA10: R85.1 U1.U5(MBA0/MA10)
MA11: R87.1 U1.R3(MCKE/MA11)
MA12: R89.1 U1.P5(MA2/MA12)
MA13: R826.1 U1.N5(MA13)
MADDR0: R65.2
MADDR1: R67.2
MADDR2: R69.2
MADDR3: R71.2
MADDR4: R73.2
MADDR5: R75.2
MADDR6: R77.2
MADDR7: R79.2
MADDR8: R81.2
MADDR9: R83.2
MADDR10: R85.2
MADDR11: R87.2
MADDR12: R89.2
MADDR13: R826.2
MBA0: R97.1 U1.U6(MRAS_N/MBA0)
MBA1: R98.1 U1.T6(MCS_N/MBA1)
MBA2: R827.1 U1.R7(MBA2)
MCAS_N: R104.1 U1.M3(MA6/MCAS_N)
MCKE: R101.1 U1.U7(MWE_N/MCKE)
MCS_N: R106.1 U1.K3(MA5/MCS_N)
MD0: R64.2 U1.T1(MD2/MD0)
MD1: R66.2 U1.U2(MD5/MD1)
MD2: R68.2 U1.R2(MD1/MD2)
MD3: R70.2 U1.U3(MD7/MD3)
MD4: R72.2 U1.T3(MD6/MD4)
MD5: R74.2 U1.R1(MD0/MD5)
MD6: R76.2 U1.T2(MD4/MD6)
MD7: R78.2 U1.U1(MD3/MD7)
MD8: R80.2 U1.M1(MD9/MD8)
MD9: R82.2 U1.J2(MD14/MD9)
MD10: R84.2 U1.L1(MD11/MD10)
MD11: R86.2 U1.K2(MD12/MD11)
MD12: R88.2 U1.K1(MD13/MD12)
MD13: R90.2 U1.L2(MD10/MD13)
MD14: R91.2 U1.J1(MD15/MD14)
MD15: R92.2 U1.M2(MD8/MD15)
MDATA0: R64.1
MDATA1: R66.1
MDATA2: R68.1
MDATA3: R70.1
MDATA4: R72.1
MDATA5: R74.1
MDATA6: R76.1
MDATA7: R78.1
MDATA8: R80.1
MDATA9: R82.1
MDATA10: R84.1
MDATA11: R86.1
MDATA12: R88.1
MDATA13: R90.1
MDATA14: R91.1
MDATA15: R92.1
MDQM0: R95.1 U1.U4(MDQM0)
MDQM1: R96.1 U1.N2(MDQM1)
MDQS0: R93.1 U1.T4(MDQS0)
MDQS1: R94.1 U1.N1(MDQS1)
MODT: R479.1 U1.J3(MODT)
MRAS_N: R103.1 U1.L3(MA4/MRAS_N)
MWE_N: R105.1 U1.T7(MCAS_N/MWE_N)

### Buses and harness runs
bus MADDR[0..13] = port MADDR[0..13]
bus MDATA[0..15] = port MDATA[0..15]

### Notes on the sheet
- 1. 1.8V for DDR2
  2. 2.5V for DDR1
- Close to RT6352

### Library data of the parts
C70 C72 C75 C76 = CAP/0402_0
C73 = CAP/1210_1206
C820 C821 = CAP/0402_Dup1
R64-R98 R101 R103-R106 R826 R827 = RES/0402
R99 R100 R479 R812 R813 = RES/0402_Dup1
U1 = MT7620A

## Sheet 11-MT7620A RF Front End.SchDoc
size 386 x 246 mm
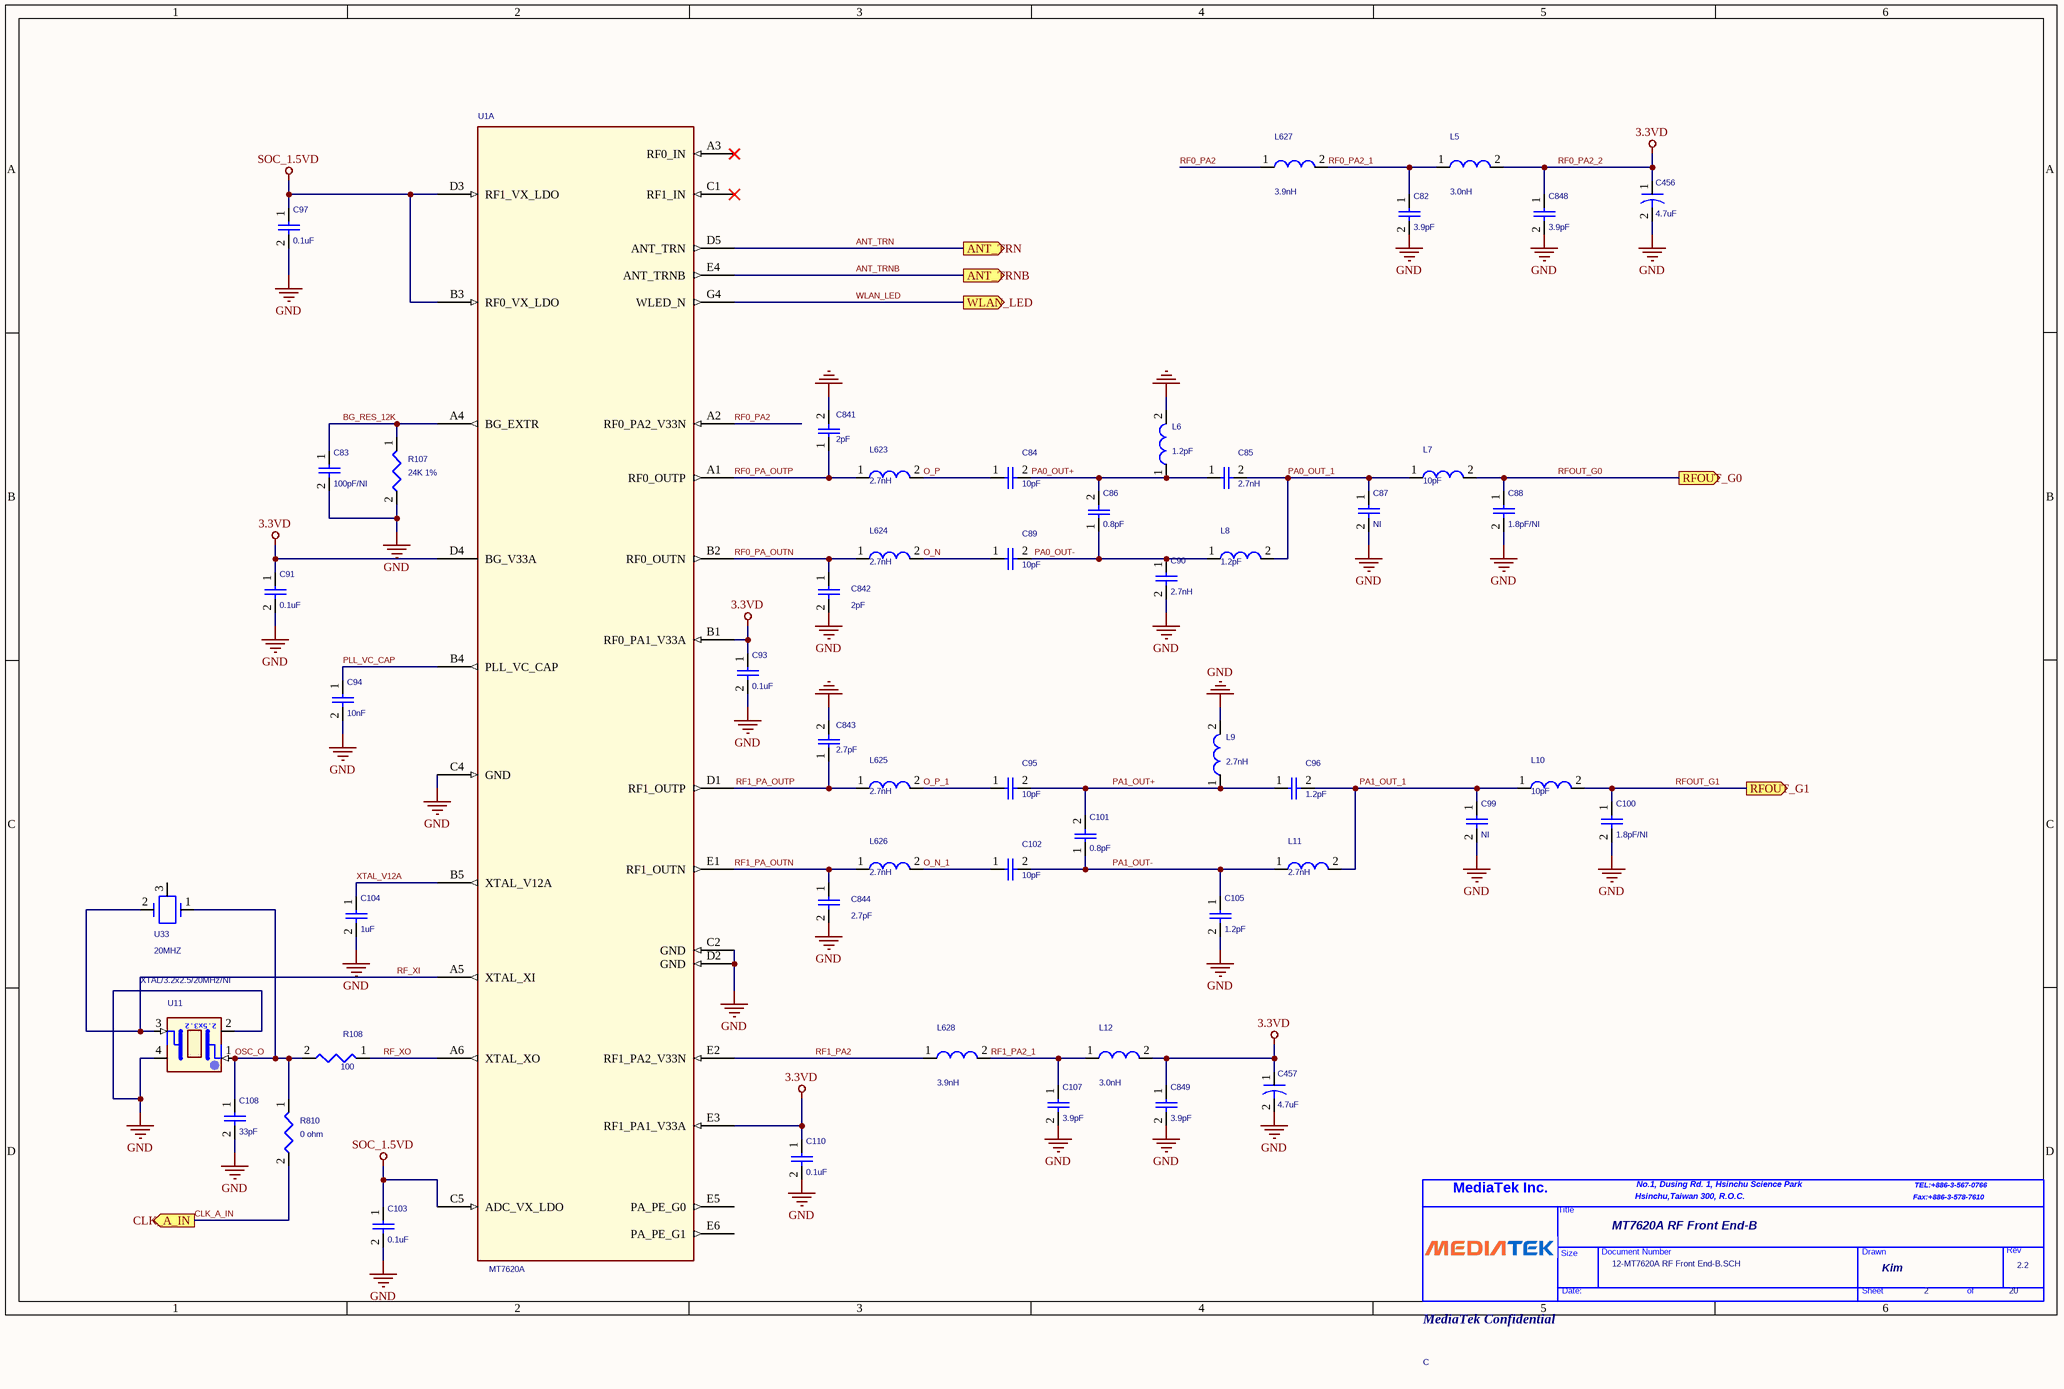
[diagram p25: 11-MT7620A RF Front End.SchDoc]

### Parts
(Parts that share a designator on the sheet are numbered #1, #2 ... from top to bottom, then left to right.)
*#19  PIM: MediaTek Confidential  Page Count: 20  Page Number: 2  Page Size: C  Title: MT7620A RF Front End-B  RevCode: 2.2  Doc: 12-MT7620A RF Front End-B.SCH  Designer: Kim  (hidden comment: TitleBlock_MTK4)  (graphical)
C82  3.9pF  [C0402]
C83  100pF/NI  [C0402]
C84  10pF  [C0402]
C85  2.7nH  [C0402]
C86  0.8pF  [C0402]
C87  NI  [C0402]
C88  1.8pF/NI  [C0402]
C89  10pF  [C0402]
C90  2.7nH  [C0402]
C91  0.1uF  [C0402]
C93  0.1uF  [C0402]
C94  10nF  [C0402]
C95  10pF  [C0402]
C96  1.2pF  [C0402]
C97  0.1uF  [C0402]
C99  NI  [C0402]
C100  1.8pF/NI  [C0402]
C101  0.8pF  [C0402]
C102  10pF  [C0402]
C103  0.1uF  [C0402]
C104  1uF  [C0402]
C105  1.2pF  [C0402]
C107  3.9pF  [C0402]
C108  33pF  [C0402]
C110  0.1uF  [C0402]
C456  4.7uF  [C0603]
C457  4.7uF  [C0603]
C841  2pF  [C0402]
C842  2pF  [C0402]
C843  2.7pF  [C0402]
C844  2.7pF  [C0402]
C848  3.9pF  [C0402]
C849  3.9pF  [C0402]
L5  3.0nH  [L0402]
L6  1.2pF  [L0402]
L7  10pF  [L0402]
L8  1.2pF  [L0402]
L9  2.7nH  [L0402]
L10  10pF  [L0402]
L11  2.7nH  [L0402]
L12  3.0nH  [L0402]
L623  2.7nH  [L0402]
L624  2.7nH  [L0402]
L625  2.7nH  [L0402]
L626  2.7nH  [L0402]
L627  3.9nH  [L0402]
L628  3.9nH  [L0402]
R107  24K 1%  [R0402]
R108  100  [R0402]
R810  0 ohm  [R0402]
U1  MT7620A  [MT7620AE2/TFBGA265/P0.65/B0.3/11X11]  (part A of 6)
U11  XTAL/3.2x2.5/20MHz/NI  [CRYS/SMD/D3.2X2.5/E3SB40/HOSONIC]
U33  20MHZ  [CRYS/DIP/D5X10.6/GB2000025/eCERA]

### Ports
ANT_TRN (out), ANT_TRNB (out), CLK_A_IN (out), RFOUT_G0 (out), RFOUT_G1 (out), WLAN_LED (out)

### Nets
3.3VD: C91.1 C93.1 C110.1 C456.1 C457.1 C848.1 C849.1 L5.2 L12.2 U1.B1(RF0_PA1_V33A) U1.D4(BG_V33A) U1.E3(RF1_PA1_V33A)  [also labelled RF0_PA2_2]
GND: C82.2 C83.2 C87.2 C88.2 C90.2 C91.2 C93.2 C94.2 C97.2 C99.2 C100.2 C103.2 C104.2 C105.2 C107.2 C108.2 C110.2 C456.2 C457.2 C841.2 C842.2 C843.2 C844.2 C848.2 C849.2 L6.2 L9.2 R107.2 U1.C2(GND) U1.C4(GND) U1.D2(GND) U11.2(NC) U11.4(NC)
SOC_1.5VD: C97.1 C103.1 U1.B3(RF0_VX_LDO) U1.C5(ADC_VX_LDO) U1.D3(RF1_VX_LDO)
ANT_TRN: U1.D5(ANT_TRN) ; port ANT_TRN
ANT_TRNB: U1.E4(ANT_TRNB) ; port ANT_TRNB
BG_RES_12K: C83.1 R107.1 U1.A4(BG_EXTR)
CLK_A_IN: R810.2 ; port CLK_A_IN
O_N: C89.1 L624.2
O_N_1: C102.1 L626.2
O_P: C84.1 L623.2
O_P_1: C95.1 L625.2
OSC_O: C108.1 R108.2 R810.1 U11.1(X1) U33.1
PA0_OUT+: C84.2 C85.1 C86.2 L6.1
PA0_OUT-: C86.1 C89.2 C90.1 L8.1
PA0_OUT_1: C85.2 C87.1 L7.1 L8.2
PA1_OUT+: C95.2 C96.1 C101.2 L9.1
PA1_OUT-: C101.1 C102.2 C105.1 L11.1
PA1_OUT_1: C96.2 C99.1 L10.1 L11.2
PLL_VC_CAP: C94.1 U1.B4(PLL_VC_CAP)
RF0_PA2: L627.1 U1.A2(RF0_PA2_V33N)
RF0_PA2_1: C82.1 L5.1 L627.2
RF0_PA_OUTN: C842.1 L624.1 U1.B2(RF0_OUTN)
RF0_PA_OUTP: C841.1 L623.1 U1.A1(RF0_OUTP)
RF1_PA2: L628.1 U1.E2(RF1_PA2_V33N)
RF1_PA2_1: C107.1 L12.1 L628.2
RF1_PA_OUTN: C844.1 L626.1 U1.E1(RF1_OUTN)
RF1_PA_OUTP: C843.1 L625.1 U1.D1(RF1_OUTP)
RF_XI: U1.A5(XTAL_XI) U11.3(X2) U33.2
RF_XO: R108.1 U1.A6(XTAL_XO)
RFOUT_G0: C88.1 L7.2 ; port RFOUT_G0
RFOUT_G1: C100.1 L10.2 ; port RFOUT_G1
WLAN_LED: U1.G4(WLED_N) ; port WLAN_LED
XTAL_V12A: C104.1 U1.B5(XTAL_V12A)

Not connected (* = marked no-connect by the designer): U1 A3(RF0_IN)* C1(RF1_IN)* E5(PA_PE_G0) E6(PA_PE_G1); U33 3

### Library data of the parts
C82 C84-C90 C93 C95 C96 C99-C102 C105 C107 C110 C848 C849 = CAP/0402_1
C83 C91 C94 C97 C103 C104 C108 = CAP/0402_0
C456 C457 = CAP/0603
C841-C844 = CAP/0402
L5-L12 L623-L628 = L/0402
R107 R810 = RES/0402_2
R108 = RES/0402_3
U11 = XTAL_3.2x2.5
U33 = XTAL(20MHZ)_1: Parnt_desc: XTAL 20MHz 30ppm HC-49/U; Parent: 24-020060-40

## Sheet 6-LED.SchDoc
size 386 x 246 mm
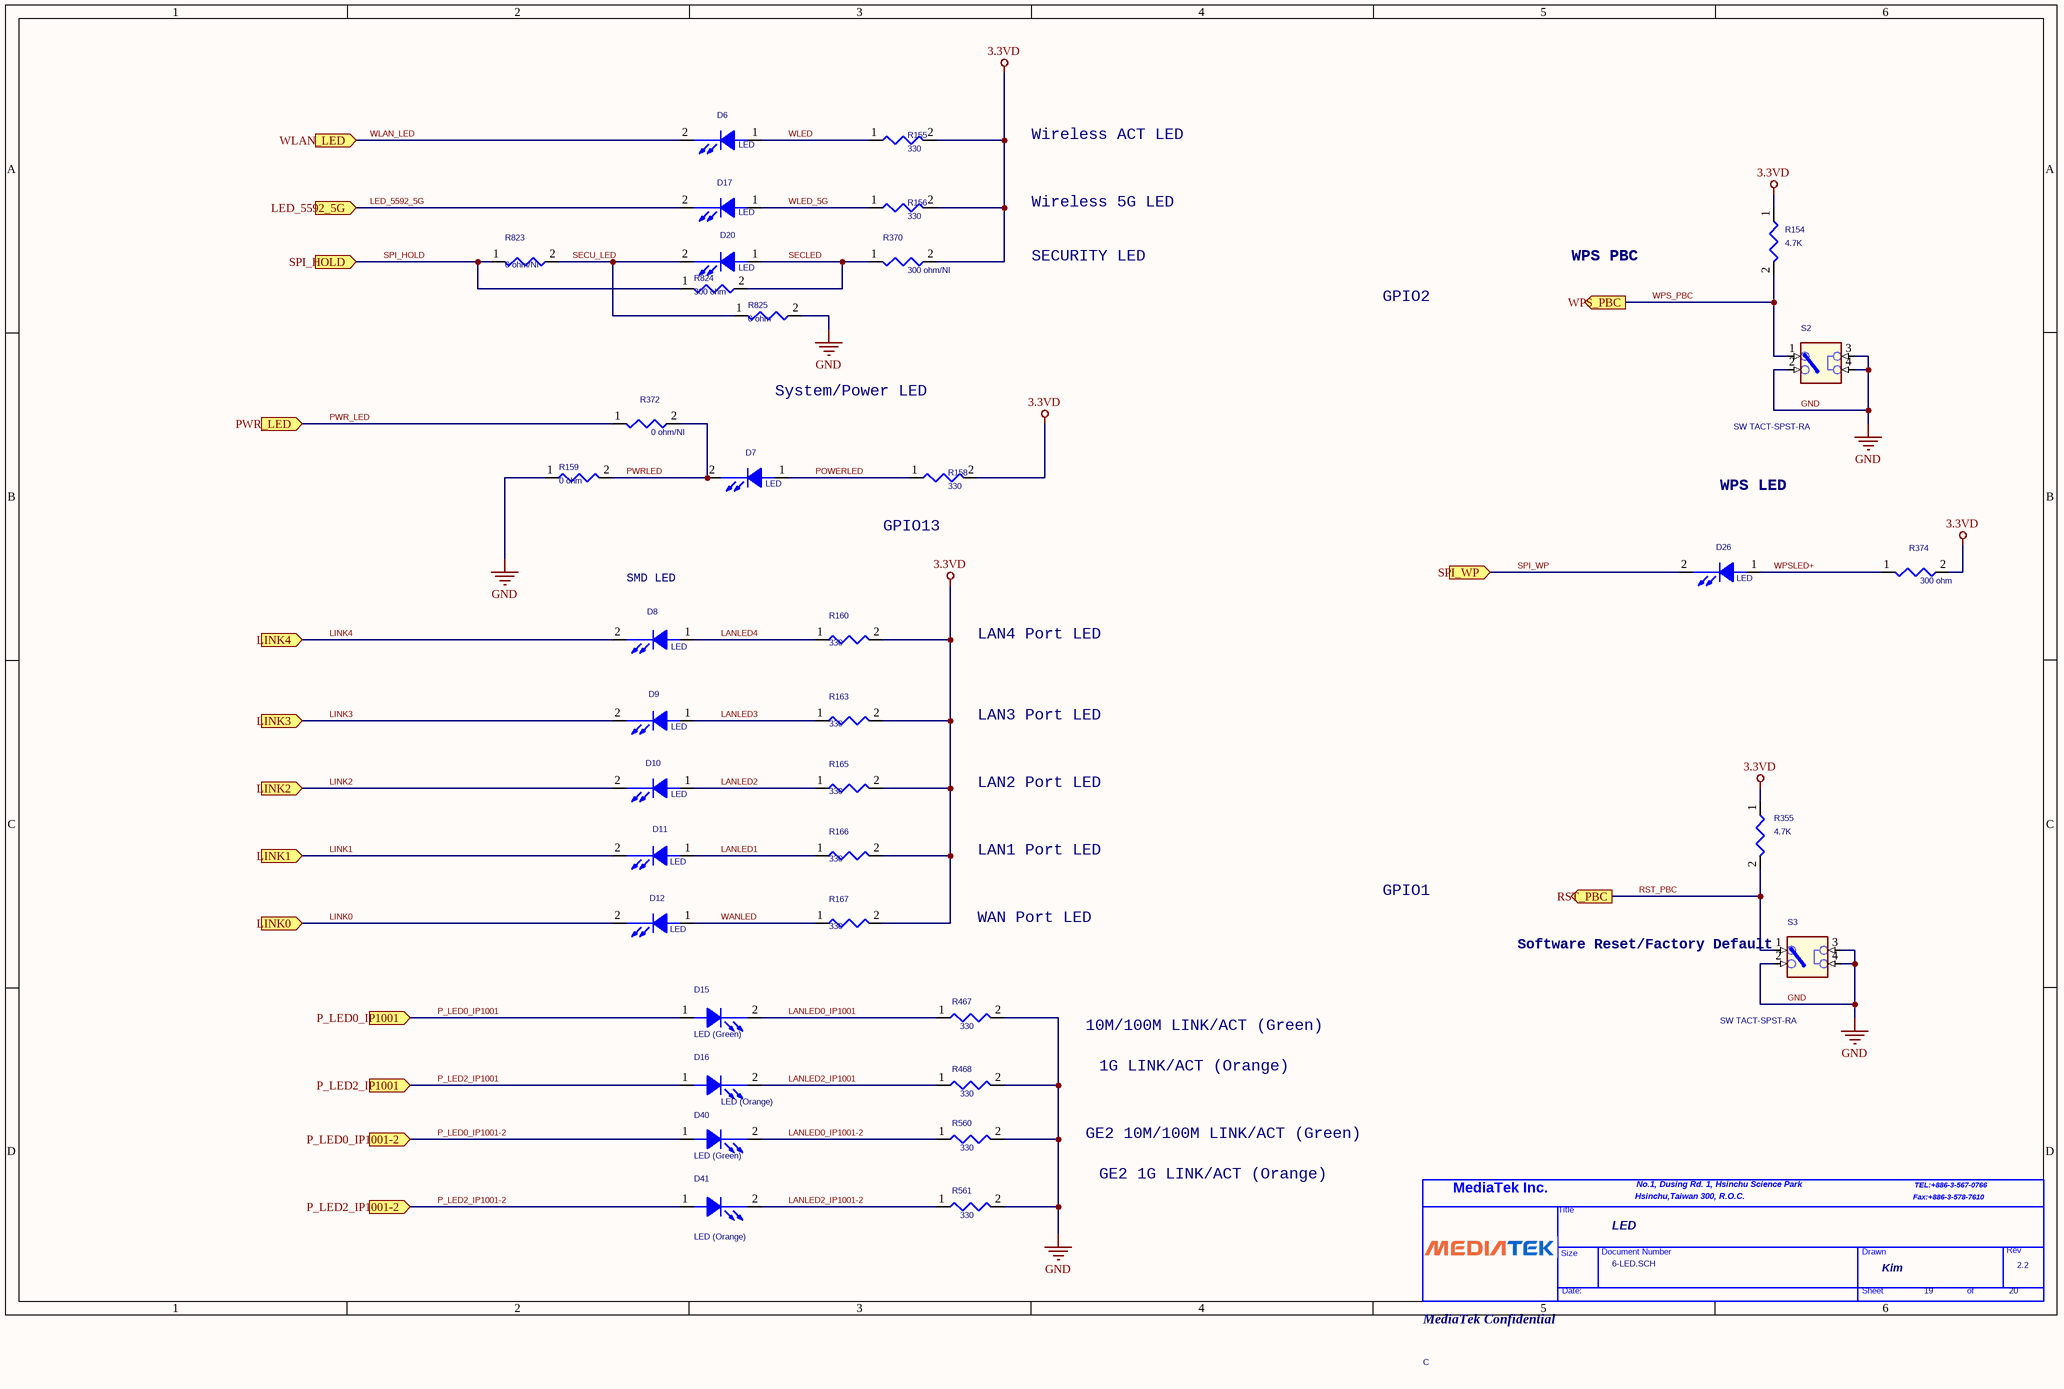
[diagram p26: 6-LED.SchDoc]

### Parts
(Parts that share a designator on the sheet are numbered #1, #2 ... from top to bottom, then left to right.)
*#20  PIM: MediaTek Confidential  Page Count: 20  Page Number: 19  Page Size: C  Title: LED  RevCode: 2.2  Doc: 6-LED.SCH  Designer: Kim  (hidden comment: TitleBlock_MTK4)  (graphical)
D6  LED  [C0603]
D7  LED  [C0603]
D8  LED  [C0603]
D9  LED  [C0603]
D10  LED  [C0603]
D11  LED  [C0603]
D12  LED  [C0603]
D15  LED (Green)  [C0603]
D16  LED (Orange)  [C0603]
D17  LED  [C0603]
D20  LED  [C0603]
D26  LED  [C0603]
D40  LED (Green)  [C0603]
D41  LED (Orange)  [C0603]
R154  4.7K  [R0402]
R155  330  [R0402]
R156  330  [R0402]
R158  330  [R0402]
R159  0 ohm  [R0402]
R160  330  [R0402]
R163  330  [R0402]
R165  330  [R0402]
R166  330  [R0402]
R167  330  [R0402]
R355  4.7K  [R0402]
R370  300 ohm/NI  [R0402]
R372  0 ohm/NI  [R0402]
R374  300 ohm  [R0402]
R467  330  [R0402]
R468  330  [R0402]
R560  330  [R0402]
R561  330  [R0402]
R823  0 ohm/NI  [R0402]
R824  300 ohm  [R0402]
R825  0 ohm  [R0402]
S2  SW TACT-SPST-RA  [SW/4P/DIP/TS02-CN-PF]
S3  SW TACT-SPST-RA  [SW/4P/DIP/TS02-CN-PF]

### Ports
LED_5592_5G (in), LINK0 (in), LINK1 (in), LINK2 (in), LINK3 (in), LINK4 (in), P_LED0_IP1001 (in), P_LED0_IP1001-2 (in), P_LED2_IP1001 (in), P_LED2_IP1001-2 (in), PWR_LED (in), RST_PBC (out), SPI_HOLD (in), SPI_WP (in), WLAN_LED (in), WPS_PBC (out)

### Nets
3.3VD: R154.1 R155.2 R156.2 R158.2 R160.2 R163.2 R165.2 R166.2 R167.2 R355.1 R370.2 R374.2
GND: R159.1 R467.2 R468.2 R560.2 R561.2 R825.2 S2.2 S2.3 S2.4 S3.2 S3.3 S3.4
LANLED0_IP1001: D15.2(CATHODE) R467.1
LANLED0_IP1001-2: D40.2(CATHODE) R560.1
LANLED1: D11.1(ANODE) R166.1
LANLED2: D10.1(ANODE) R165.1
LANLED2_IP1001: D16.2(CATHODE) R468.1
LANLED2_IP1001-2: D41.2(CATHODE) R561.1
LANLED3: D9.1(ANODE) R163.1
LANLED4: D8.1(ANODE) R160.1
LED_5592_5G: D17.2(CATHODE) ; port LED_5592_5G
LINK0: D12.2(CATHODE) ; port LINK0
LINK1: D11.2(CATHODE) ; port LINK1
LINK2: D10.2(CATHODE) ; port LINK2
LINK3: D9.2(CATHODE) ; port LINK3
LINK4: D8.2(CATHODE) ; port LINK4
P_LED0_IP1001: D15.1(ANODE) ; port P_LED0_IP1001
P_LED0_IP1001-2: D40.1(ANODE) ; port P_LED0_IP1001-2
P_LED2_IP1001: D16.1(ANODE) ; port P_LED2_IP1001
P_LED2_IP1001-2: D41.1(ANODE) ; port P_LED2_IP1001-2
POWERLED: D7.1(ANODE) R158.1
PWR_LED: R372.1 ; port PWR_LED
PWRLED: D7.2(CATHODE) R159.2 R372.2
RST_PBC: R355.2 S3.1 ; port RST_PBC
SECLED: D20.1(ANODE) R370.1 R824.2
SECU_LED: D20.2(CATHODE) R823.2 R825.1
SPI_HOLD: R823.1 R824.1 ; port SPI_HOLD
SPI_WP: D26.2(CATHODE) ; port SPI_WP
WANLED: D12.1(ANODE) R167.1
WLAN_LED: D6.2(CATHODE) ; port WLAN_LED
WLED: D6.1(ANODE) R155.1
WLED_5G: D17.1(ANODE) R156.1
WPS_PBC: R154.2 S2.1 ; port WPS_PBC
WPSLED+: D26.1(ANODE) R374.1

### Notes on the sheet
- Wireless ACT LED
- Wireless 5G LED
- SECURITY LED
- WPS PBC
- GPIO2
- System/Power LED
- (near R158) GPIO13
- WPS LED
- SMD LED
- LAN4 Port LED
- LAN3 Port LED
- LAN2 Port LED
- LAN1 Port LED
- WAN Port LED
- GPIO1
- (near S3) Software Reset/Factory Default
- 10M/100M LINK/ACT (Green)
- 1G LINK/ACT (Orange)
- GE2 10M/100M LINK/ACT (Green)
- GE2 1G LINK/ACT (Orange)

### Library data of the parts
D6-D12 D15-D17 D20 D26 D40 D41 = LED/0603
R154 = RES/0402_6
R155 R156 R158-R160 R163 R165-R167 = RES/0402_5
R355 R467 R468 R560 R561 = RES/0402_Dup2
R370 R372 R374 R823-R825 = RES/0402_3

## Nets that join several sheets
1.8VD: 22-DDR-CFG (30 pins), 5-POWER-RESET (C45.1 C47.1 R17.1 U5.2), 12-MT7620A DDR I_F-B (10 pins)
3.3VD: 23-CONFIG (8 pins), 21-SPI Flash (5 pins), 32-RT5592EP-solt-5G (12 pins), 5-POWER-RESET (13 pins), 18-GPHY2-IP1001 (16 pins), 17-GPHY1-IP1001 (16 pins), 16-MT7620A Power-F (8 pins), 15-MT7620A Ethernet-E (12 pins), 14-MT7620A USB and PCIE (C39.1 C40.1 U1.E10 U1.E13), 13-MT7620A Peripheral-C (12 pins), 11-MT7620A RF Front End (12 pins), 6-LED (12 pins)
5V: 32-RT5592EP-solt-5G (C219.1 J12.1 R417.2), 5-POWER-RESET (7 pins)
5VA: 32-RT5592EP-solt-5G (R820.2), 5-POWER-RESET (7 pins)
5VD_0: 5-POWER-RESET (C24.1 C366.1 R356.2), 14-MT7620A USB and PCIE (USB1.1)
CHGND_GE_A: 43-GE2-XMER-RJ45 (5 pins), 42-GE-XMER-RJ45 (5 pins)
GND: 23-CONFIG (9 pins), 22-DDR-CFG (30 pins), 21-SPI Flash (C137.2 U18.4), 32-RT5592EP-solt-5G (31 pins), 31-Antenna (CON53.2 CON53.3 CON54.2 CON54.3), 43-GE2-XMER-RJ45 (20 pins), 42-GE-XMER-RJ45 (20 pins), 41-XMER-RJ45 (11 pins), 5-POWER-RESET (50 pins), 18-GPHY2-IP1001 (41 pins), 17-GPHY1-IP1001 (40 pins), 16-MT7620A Power-F (20 pins), 15-MT7620A Ethernet-E (17 pins), 14-MT7620A USB and PCIE (25 pins), 13-MT7620A Peripheral-C (35 pins), 12-MT7620A DDR I_F-B (23 pins), 11-MT7620A RF Front End (33 pins), 6-LED (12 pins)
P_AVDD_IP1001: 42-GE-XMER-RJ45 (L616.1), 17-GPHY1-IP1001 (15 pins)
P_AVDD_IP1001-2: 43-GE2-XMER-RJ45 (L622.1), 18-GPHY2-IP1001 (15 pins)
SOC_1.2VD: 16-MT7620A Power-F (16 pins), 15-MT7620A Ethernet-E (5 pins), 14-MT7620A USB and PCIE (6 pins), 12-MT7620A DDR I_F-B (C72.1 U1.M5 U1.N4)
SOC_1.5VD: 16-MT7620A Power-F (11 pins), 11-MT7620A RF Front End (5 pins)
ANT_TRN: 23-CONFIG (R128.2 R130.2), 11-MT7620A RF Front End (U1.D5)
ANT_TRNB: 23-CONFIG (R129.2 R131.2), 11-MT7620A RF Front End (U1.E4)
APCK_RFCKO_N: 32-RT5592EP-solt-5G (J6.13), 14-MT7620A USB and PCIE (R382.2)
APCK_RFCKO_P: 32-RT5592EP-solt-5G (J6.11), 14-MT7620A USB and PCIE (R383.2)
CHANNEL_A+: 42-GE-XMER-RJ45 (C706.1 R783.2 T600.12), 17-GPHY1-IP1001 (U607.18)
CHANNEL_A+_2: 43-GE2-XMER-RJ45 (C718.1 R791.2 T601.12), 18-GPHY2-IP1001 (U609.18)
CHANNEL_A-: 42-GE-XMER-RJ45 (C707.1 R784.2 T600.11), 17-GPHY1-IP1001 (U607.19)
CHANNEL_A-_2: 43-GE2-XMER-RJ45 (C719.1 R792.2 T601.11), 18-GPHY2-IP1001 (U609.19)
CHANNEL_B+: 42-GE-XMER-RJ45 (C708.1 R785.2 T600.9), 17-GPHY1-IP1001 (U607.21)
CHANNEL_B+_2: 43-GE2-XMER-RJ45 (C720.1 R793.2 T601.9), 18-GPHY2-IP1001 (U609.21)
CHANNEL_B-: 42-GE-XMER-RJ45 (C709.1 R786.2 T600.8), 17-GPHY1-IP1001 (U607.22)
CHANNEL_B-_2: 43-GE2-XMER-RJ45 (C721.1 R794.2 T601.8), 18-GPHY2-IP1001 (U609.22)
CHANNEL_C+: 42-GE-XMER-RJ45 (C710.1 R787.2 T600.6), 17-GPHY1-IP1001 (U607.26)
CHANNEL_C+_2: 43-GE2-XMER-RJ45 (C722.1 R799.2 T601.6), 18-GPHY2-IP1001 (U609.26)
CHANNEL_C-: 42-GE-XMER-RJ45 (C711.1 R788.2 T600.5), 17-GPHY1-IP1001 (U607.27)
CHANNEL_C-_2: 43-GE2-XMER-RJ45 (C723.1 R800.2 T601.5), 18-GPHY2-IP1001 (U609.27)
CHANNEL_D+: 42-GE-XMER-RJ45 (C712.1 R789.2 T600.3), 17-GPHY1-IP1001 (U607.29)
CHANNEL_D+_2: 43-GE2-XMER-RJ45 (C724.1 R801.2 T601.3), 18-GPHY2-IP1001 (U609.29)
CHANNEL_D-: 42-GE-XMER-RJ45 (C713.1 R790.2 T600.2), 17-GPHY1-IP1001 (U607.30)
CHANNEL_D-_2: 43-GE2-XMER-RJ45 (C725.1 R802.2 T601.2), 18-GPHY2-IP1001 (U609.30)
CLK_25M: 17-GPHY1-IP1001 (R832.2), 13-MT7620A Peripheral-C (R831.2)
CLK_A_IN: 32-RT5592EP-solt-5G (J6.51), 11-MT7620A RF Front End (R810.2)
CLK_N: 22-DDR-CFG (C127.2 R150.2 U22.K8), 12-MT7620A DDR I_F-B (R100.2)
CLK_P: 22-DDR-CFG (C127.1 R150.1 U22.J8), 12-MT7620A DDR I_F-B (R99.2)
CPURST_N: 5-POWER-RESET (R15.2), 13-MT7620A Peripheral-C (U1.C6)
DDR_BA0: 22-DDR-CFG (U22.L2), 12-MT7620A DDR I_F-B (R97.2)
DDR_BA1: 22-DDR-CFG (U22.L3), 12-MT7620A DDR I_F-B (R98.2)
DDR_BA2: 22-DDR-CFG (U22.L1), 12-MT7620A DDR I_F-B (R827.2)
DDR_CASN: 22-DDR-CFG (U22.L7), 12-MT7620A DDR I_F-B (R104.2)
DDR_CSN: 22-DDR-CFG (U22.L8), 12-MT7620A DDR I_F-B (R106.2)
DDR_MCKE: 22-DDR-CFG (U22.K2), 12-MT7620A DDR I_F-B (R101.2)
DDR_MDQM0: 22-DDR-CFG (U22.F3), 12-MT7620A DDR I_F-B (R95.2)
DDR_MDQM1: 22-DDR-CFG (U22.B3), 12-MT7620A DDR I_F-B (R96.2)
DDR_MDQS0: 22-DDR-CFG (U22.F7), 12-MT7620A DDR I_F-B (R93.2)
DDR_MDQS1: 22-DDR-CFG (U22.B7), 12-MT7620A DDR I_F-B (R94.2)
DDR_MODT: 22-DDR-CFG (U22.K9), 12-MT7620A DDR I_F-B (R479.2)
DDR_RASN: 22-DDR-CFG (U22.K7), 12-MT7620A DDR I_F-B (R103.2)
DDR_WEN: 22-DDR-CFG (U22.K3), 12-MT7620A DDR I_F-B (R105.2)
GE2_RXCLK: 18-GPHY2-IP1001 (R736.1 R737.2), 15-MT7620A Ethernet-E (U1.D14)
GE2_RXD0: 18-GPHY2-IP1001 (R730.1), 15-MT7620A Ethernet-E (U1.F15)
GE2_RXD1: 18-GPHY2-IP1001 (R727.1), 15-MT7620A Ethernet-E (U1.E15)
GE2_RXD2: 18-GPHY2-IP1001 (R724.1), 15-MT7620A Ethernet-E (U1.F14)
GE2_RXD3: 18-GPHY2-IP1001 (R722.1), 15-MT7620A Ethernet-E (U1.E14)
GE2_RXDV: 18-GPHY2-IP1001 (R729.1), 15-MT7620A Ethernet-E (U1.D15)
GE_2_TXCLK: 18-GPHY2-IP1001 (U609.57), 15-MT7620A Ethernet-E (R558.1 R559.2)
GE_2_TXD0: 18-GPHY2-IP1001 (U609.59), 15-MT7620A Ethernet-E (R556.1)
GE_2_TXD1: 18-GPHY2-IP1001 (U609.60), 15-MT7620A Ethernet-E (R555.1)
GE_2_TXD2: 18-GPHY2-IP1001 (U609.61), 15-MT7620A Ethernet-E (R554.1)
GE_2_TXD3: 18-GPHY2-IP1001 (U609.62), 15-MT7620A Ethernet-E (R553.1)
GE_2_TXEN: 18-GPHY2-IP1001 (U609.58), 15-MT7620A Ethernet-E (R557.1)
GE_MDC: 18-GPHY2-IP1001 (R735.2), 17-GPHY1-IP1001 (R707.2), 15-MT7620A Ethernet-E (U1.k14)
GE_MDIO: 18-GPHY2-IP1001 (R738.2), 17-GPHY1-IP1001 (R711.2), 15-MT7620A Ethernet-E (R221.2 U1.k15)
GE_RXCLK: 17-GPHY1-IP1001 (R708.1 R709.2), 15-MT7620A Ethernet-E (U1.D17)
GE_RXD0: 17-GPHY1-IP1001 (R703.1), 15-MT7620A Ethernet-E (U1.E17)
GE_RXD1: 17-GPHY1-IP1001 (R697.1), 15-MT7620A Ethernet-E (U1.E16)
GE_RXD2: 17-GPHY1-IP1001 (R693.1), 15-MT7620A Ethernet-E (U1.F17)
GE_RXD3: 17-GPHY1-IP1001 (R692.1), 15-MT7620A Ethernet-E (U1.F16)
GE_RXDV: 17-GPHY1-IP1001 (R702.1), 15-MT7620A Ethernet-E (U1.D16)
GE_TXCLK: 17-GPHY1-IP1001 (U607.57), 15-MT7620A Ethernet-E (R102.1 R219.2)
GE_TXD0: 17-GPHY1-IP1001 (U607.59), 15-MT7620A Ethernet-E (R63.1)
GE_TXD1: 17-GPHY1-IP1001 (U607.60), 15-MT7620A Ethernet-E (R61.1)
GE_TXD2: 17-GPHY1-IP1001 (U607.61), 15-MT7620A Ethernet-E (R421.1)
GE_TXD3: 17-GPHY1-IP1001 (U607.62), 15-MT7620A Ethernet-E (R207.1)
GE_TXEN: 17-GPHY1-IP1001 (U607.58), 15-MT7620A Ethernet-E (R62.1)
GPIO0: 23-CONFIG (R124.2 R126.2), 13-MT7620A Peripheral-C (U1.D7)
JTAGRST_N: 5-POWER-RESET (5 pins), 15-MT7620A Ethernet-E (J13.11 R472.2)
LED_5592_5G: 32-RT5592EP-solt-5G (R415.1), 6-LED (D17.2)
LINK0: 15-MT7620A Ethernet-E (C845.1 R478.2 U1.H4), 6-LED (D12.2)
LINK1: 15-MT7620A Ethernet-E (J13.3 R476.2 U1.H3), 6-LED (D11.2)
LINK2: 15-MT7620A Ethernet-E (J13.7 R474.2 U1.H2), 6-LED (D10.2)
LINK3: 15-MT7620A Ethernet-E (J13.9 R473.2 U1.H1), 6-LED (D9.2)
LINK4: 15-MT7620A Ethernet-E (C846.1 J13.1 R477.2 U1.J4), 6-LED (D8.2)
MADDR0: 22-DDR-CFG (U22.M8), 12-MT7620A DDR I_F-B (R65.2)
MADDR1: 22-DDR-CFG (U22.M3), 12-MT7620A DDR I_F-B (R67.2)
MADDR2: 22-DDR-CFG (U22.M7), 12-MT7620A DDR I_F-B (R69.2)
MADDR3: 22-DDR-CFG (U22.N2), 12-MT7620A DDR I_F-B (R71.2)
MADDR4: 22-DDR-CFG (U22.N8), 12-MT7620A DDR I_F-B (R73.2)
MADDR5: 22-DDR-CFG (U22.N3), 12-MT7620A DDR I_F-B (R75.2)
MADDR6: 22-DDR-CFG (U22.N7), 12-MT7620A DDR I_F-B (R77.2)
MADDR7: 22-DDR-CFG (U22.P2), 12-MT7620A DDR I_F-B (R79.2)
MADDR8: 22-DDR-CFG (U22.P8), 12-MT7620A DDR I_F-B (R81.2)
MADDR9: 22-DDR-CFG (U22.P3), 12-MT7620A DDR I_F-B (R83.2)
MADDR10: 22-DDR-CFG (U22.M2), 12-MT7620A DDR I_F-B (R85.2)
MADDR11: 22-DDR-CFG (U22.P7), 12-MT7620A DDR I_F-B (R87.2)
MADDR12: 22-DDR-CFG (U22.R2), 12-MT7620A DDR I_F-B (R89.2)
MADDR13: 22-DDR-CFG (U22.R8), 12-MT7620A DDR I_F-B (R826.2)
MDATA0: 22-DDR-CFG (U22.G8), 12-MT7620A DDR I_F-B (R64.1)
MDATA1: 22-DDR-CFG (U22.G2), 12-MT7620A DDR I_F-B (R66.1)
MDATA2: 22-DDR-CFG (U22.H7), 12-MT7620A DDR I_F-B (R68.1)
MDATA3: 22-DDR-CFG (U22.H3), 12-MT7620A DDR I_F-B (R70.1)
MDATA4: 22-DDR-CFG (U22.H1), 12-MT7620A DDR I_F-B (R72.1)
MDATA5: 22-DDR-CFG (U22.H9), 12-MT7620A DDR I_F-B (R74.1)
MDATA6: 22-DDR-CFG (U22.F1), 12-MT7620A DDR I_F-B (R76.1)
MDATA7: 22-DDR-CFG (U22.F9), 12-MT7620A DDR I_F-B (R78.1)
MDATA8: 22-DDR-CFG (U22.C8), 12-MT7620A DDR I_F-B (R80.1)
MDATA9: 22-DDR-CFG (U22.C2), 12-MT7620A DDR I_F-B (R82.1)
MDATA10: 22-DDR-CFG (U22.D7), 12-MT7620A DDR I_F-B (R84.1)
MDATA11: 22-DDR-CFG (U22.D3), 12-MT7620A DDR I_F-B (R86.1)
MDATA12: 22-DDR-CFG (U22.D1), 12-MT7620A DDR I_F-B (R88.1)
MDATA13: 22-DDR-CFG (U22.D9), 12-MT7620A DDR I_F-B (R90.1)
MDATA14: 22-DDR-CFG (U22.B1), 12-MT7620A DDR I_F-B (R91.1)
MDATA15: 22-DDR-CFG (U22.B9), 12-MT7620A DDR I_F-B (R92.1)
P_LED0_IP1001: 17-GPHY1-IP1001 (U607.13), 6-LED (D15.1)
P_LED0_IP1001-2: 18-GPHY2-IP1001 (U609.13), 6-LED (D40.1)
P_LED2_IP1001: 17-GPHY1-IP1001 (U607.15), 6-LED (D16.1)
P_LED2_IP1001-2: 18-GPHY2-IP1001 (U609.15), 6-LED (D41.1)
PCIE_RST#: 32-RT5592EP-solt-5G (C217.1 J6.22), 14-MT7620A USB and PCIE (U1.D10)
PCIE_RXN: 32-RT5592EP-solt-5G (J6.23), 14-MT7620A USB and PCIE (U1.B9)
PCIE_RXP: 32-RT5592EP-solt-5G (J6.25), 14-MT7620A USB and PCIE (U1.A9)
PCIE_TX_N: 32-RT5592EP-solt-5G (J6.33), 14-MT7620A USB and PCIE (C81.2)
PCIE_TX_P: 32-RT5592EP-solt-5G (J6.31), 14-MT7620A USB and PCIE (C80.2)
PMCT_HV_GE: 43-GE2-XMER-RJ45 (5 pins), 42-GE-XMER-RJ45 (5 pins)
PWR_LED: 13-MT7620A Peripheral-C (U1.U13), 6-LED (R372.1)
RFOUT_G0: 31-Antenna (CON53.1), 11-MT7620A RF Front End (C88.1 L7.2)
RFOUT_G1: 31-Antenna (CON54.1), 11-MT7620A RF Front End (C100.1 L10.2)
RST_PBC: 13-MT7620A Peripheral-C (R809.1), 6-LED (R355.2 S3.1)
RXIM0: 41-XMER-RJ45 (U14.9), 15-MT7620A Ethernet-E (U1.T15)
RXIM1: 41-XMER-RJ45 (U14.1), 15-MT7620A Ethernet-E (U1.R17)
RXIM2: 41-XMER-RJ45 (U12.9), 15-MT7620A Ethernet-E (U1.P17)
RXIM3: 41-XMER-RJ45 (U12.2), 15-MT7620A Ethernet-E (U1.M14)
RXIM4: 41-XMER-RJ45 (U16.5), 15-MT7620A Ethernet-E (U1.N17)
RXIP0: 41-XMER-RJ45 (U14.10), 15-MT7620A Ethernet-E (U1.U15)
RXIP1: 41-XMER-RJ45 (U14.2), 15-MT7620A Ethernet-E (U1.R16)
RXIP2: 41-XMER-RJ45 (U12.10), 15-MT7620A Ethernet-E (U1.P16)
RXIP3: 41-XMER-RJ45 (U12.1), 15-MT7620A Ethernet-E (U1.M15)
RXIP4: 41-XMER-RJ45 (U16.7), 15-MT7620A Ethernet-E (U1.N16)
SPI_CLK: 23-CONFIG (R125.2 R127.2), 21-SPI Flash (U18.6), 13-MT7620A Peripheral-C (SR1.2)
SPI_CS0: 21-SPI Flash (R170.1 U18.1), 13-MT7620A Peripheral-C (U1.C7)
SPI_HOLD: 23-CONFIG (R142.2), 13-MT7620A Peripheral-C (U1.B8), 6-LED (R823.1 R824.1)
SPI_MISO: 21-SPI Flash (U18.2), 13-MT7620A Peripheral-C (U1.C8)
SPI_MOSI: 23-CONFIG (R133.2 R135.2), 21-SPI Flash (U18.5), 13-MT7620A Peripheral-C (U1.A8)
SPI_WP: 23-CONFIG (R136.2), 13-MT7620A Peripheral-C (U1.B7), 6-LED (D26.2)
TXOM0: 41-XMER-RJ45 (U14.6), 15-MT7620A Ethernet-E (U1.U17)
TXOM1: 41-XMER-RJ45 (U14.4), 15-MT7620A Ethernet-E (U1.T17)
TXOM2: 41-XMER-RJ45 (U12.7), 15-MT7620A Ethernet-E (U1.P15)
TXOM3: 41-XMER-RJ45 (U12.4), 15-MT7620A Ethernet-E (U1.N14)
TXOM4: 41-XMER-RJ45 (U16.1), 15-MT7620A Ethernet-E (U1.M17)
TXOP0: 41-XMER-RJ45 (U14.7), 15-MT7620A Ethernet-E (U1.U16)
TXOP1: 41-XMER-RJ45 (U14.5), 15-MT7620A Ethernet-E (U1.T16)
TXOP2: 41-XMER-RJ45 (U12.6), 15-MT7620A Ethernet-E (U1.P14)
TXOP3: 41-XMER-RJ45 (U12.5), 15-MT7620A Ethernet-E (U1.N15)
TXOP4: 41-XMER-RJ45 (U16.3), 15-MT7620A Ethernet-E (U1.M16)
UART_TX: 23-CONFIG (R137.2 R139.2), 13-MT7620A Peripheral-C (J2.3 U1.P13)
WDT_RST_N: 5-POWER-RESET (R343.2 U4.3), 13-MT7620A Peripheral-C (U1.D6)
WLAN_LED: 23-CONFIG (C847.1 R132.2 R134.2), 11-MT7620A RF Front End (U1.G4), 6-LED (D6.2)
WPS_PBC: 13-MT7620A Peripheral-C (R808.1), 6-LED (R154.2 S2.1)
X1_IP1001-CO: 18-GPHY2-IP1001 (R745.2), 17-GPHY1-IP1001 (R746.2)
